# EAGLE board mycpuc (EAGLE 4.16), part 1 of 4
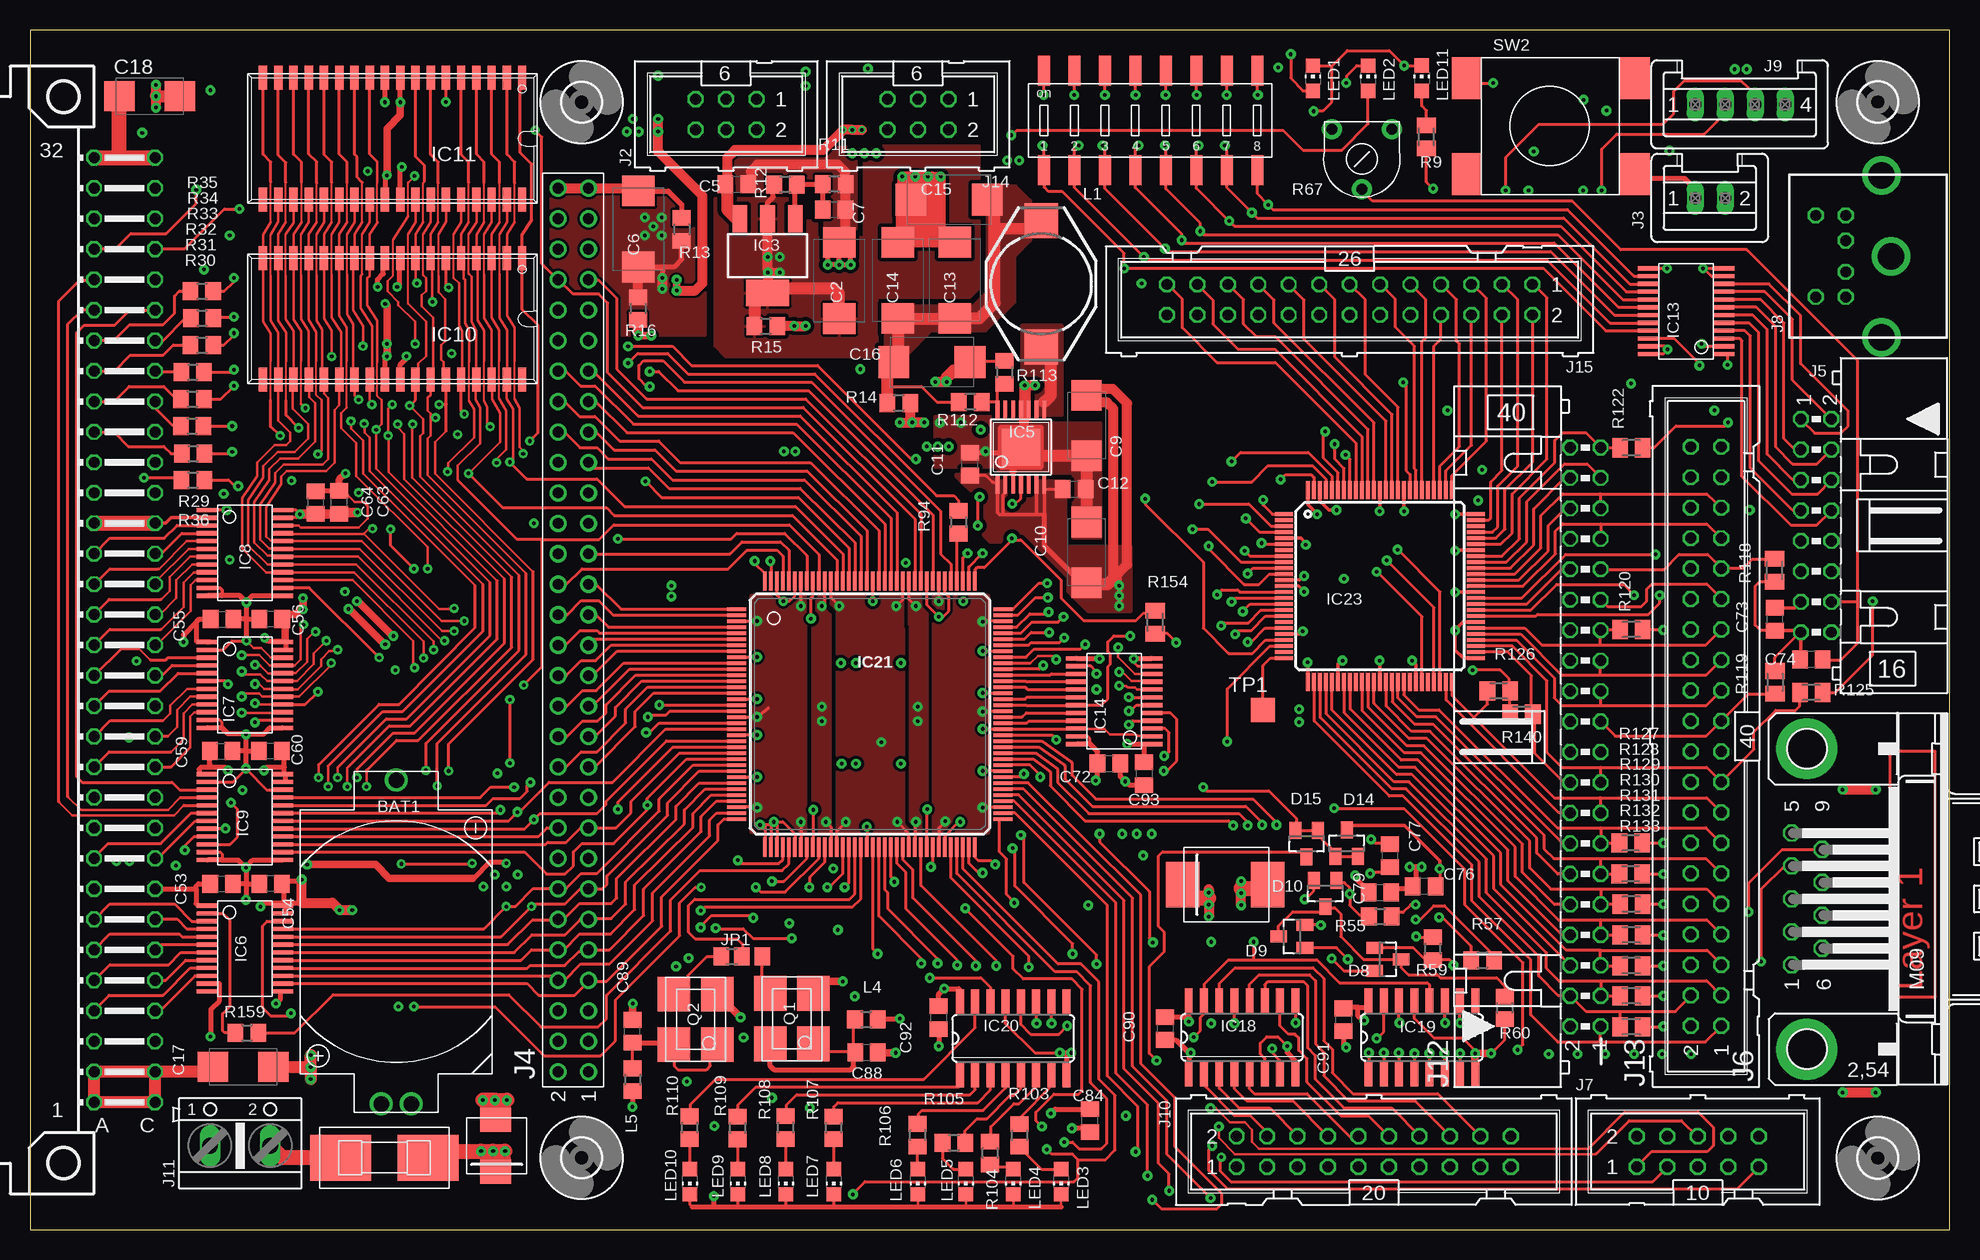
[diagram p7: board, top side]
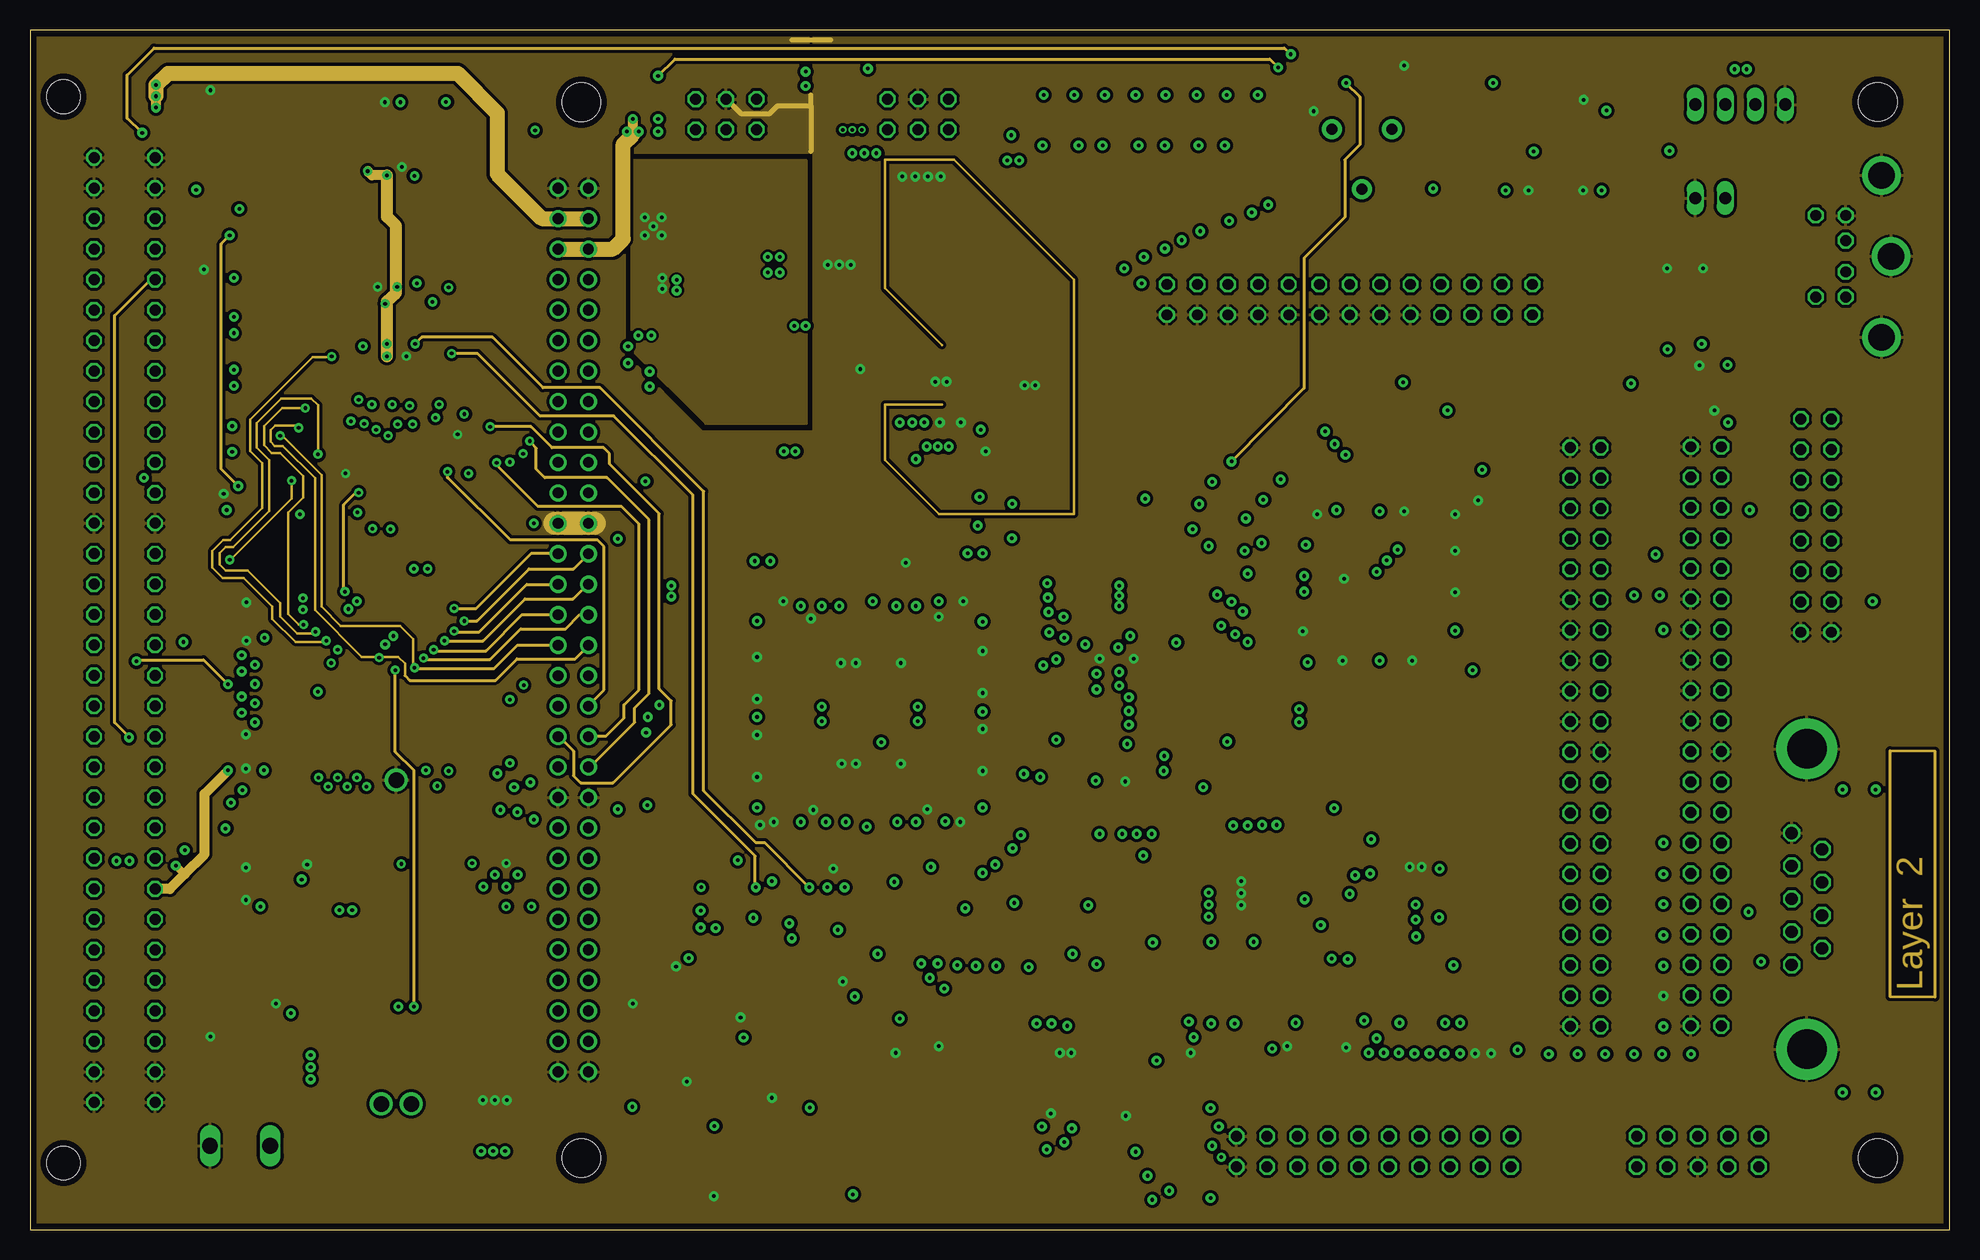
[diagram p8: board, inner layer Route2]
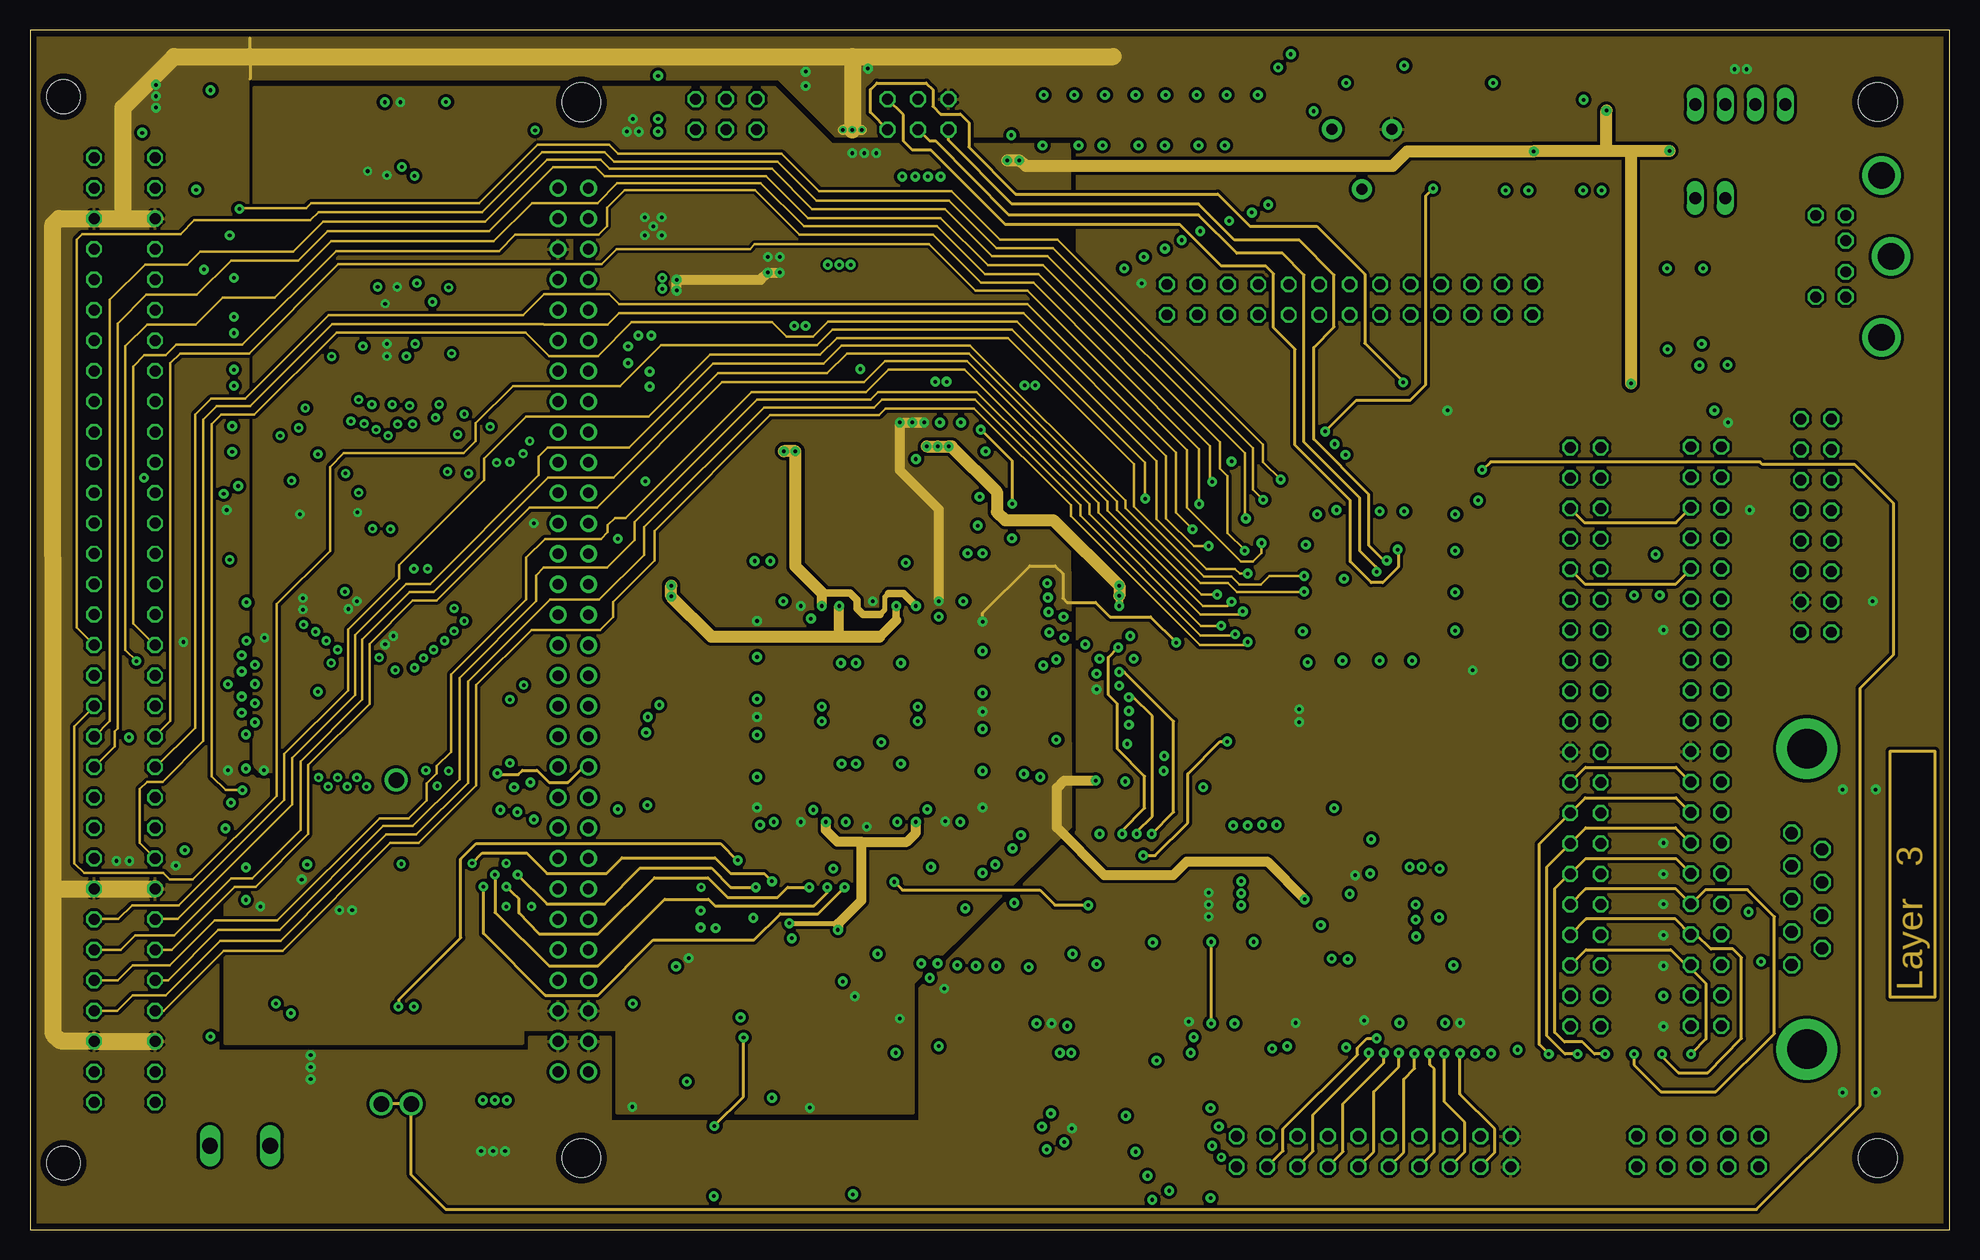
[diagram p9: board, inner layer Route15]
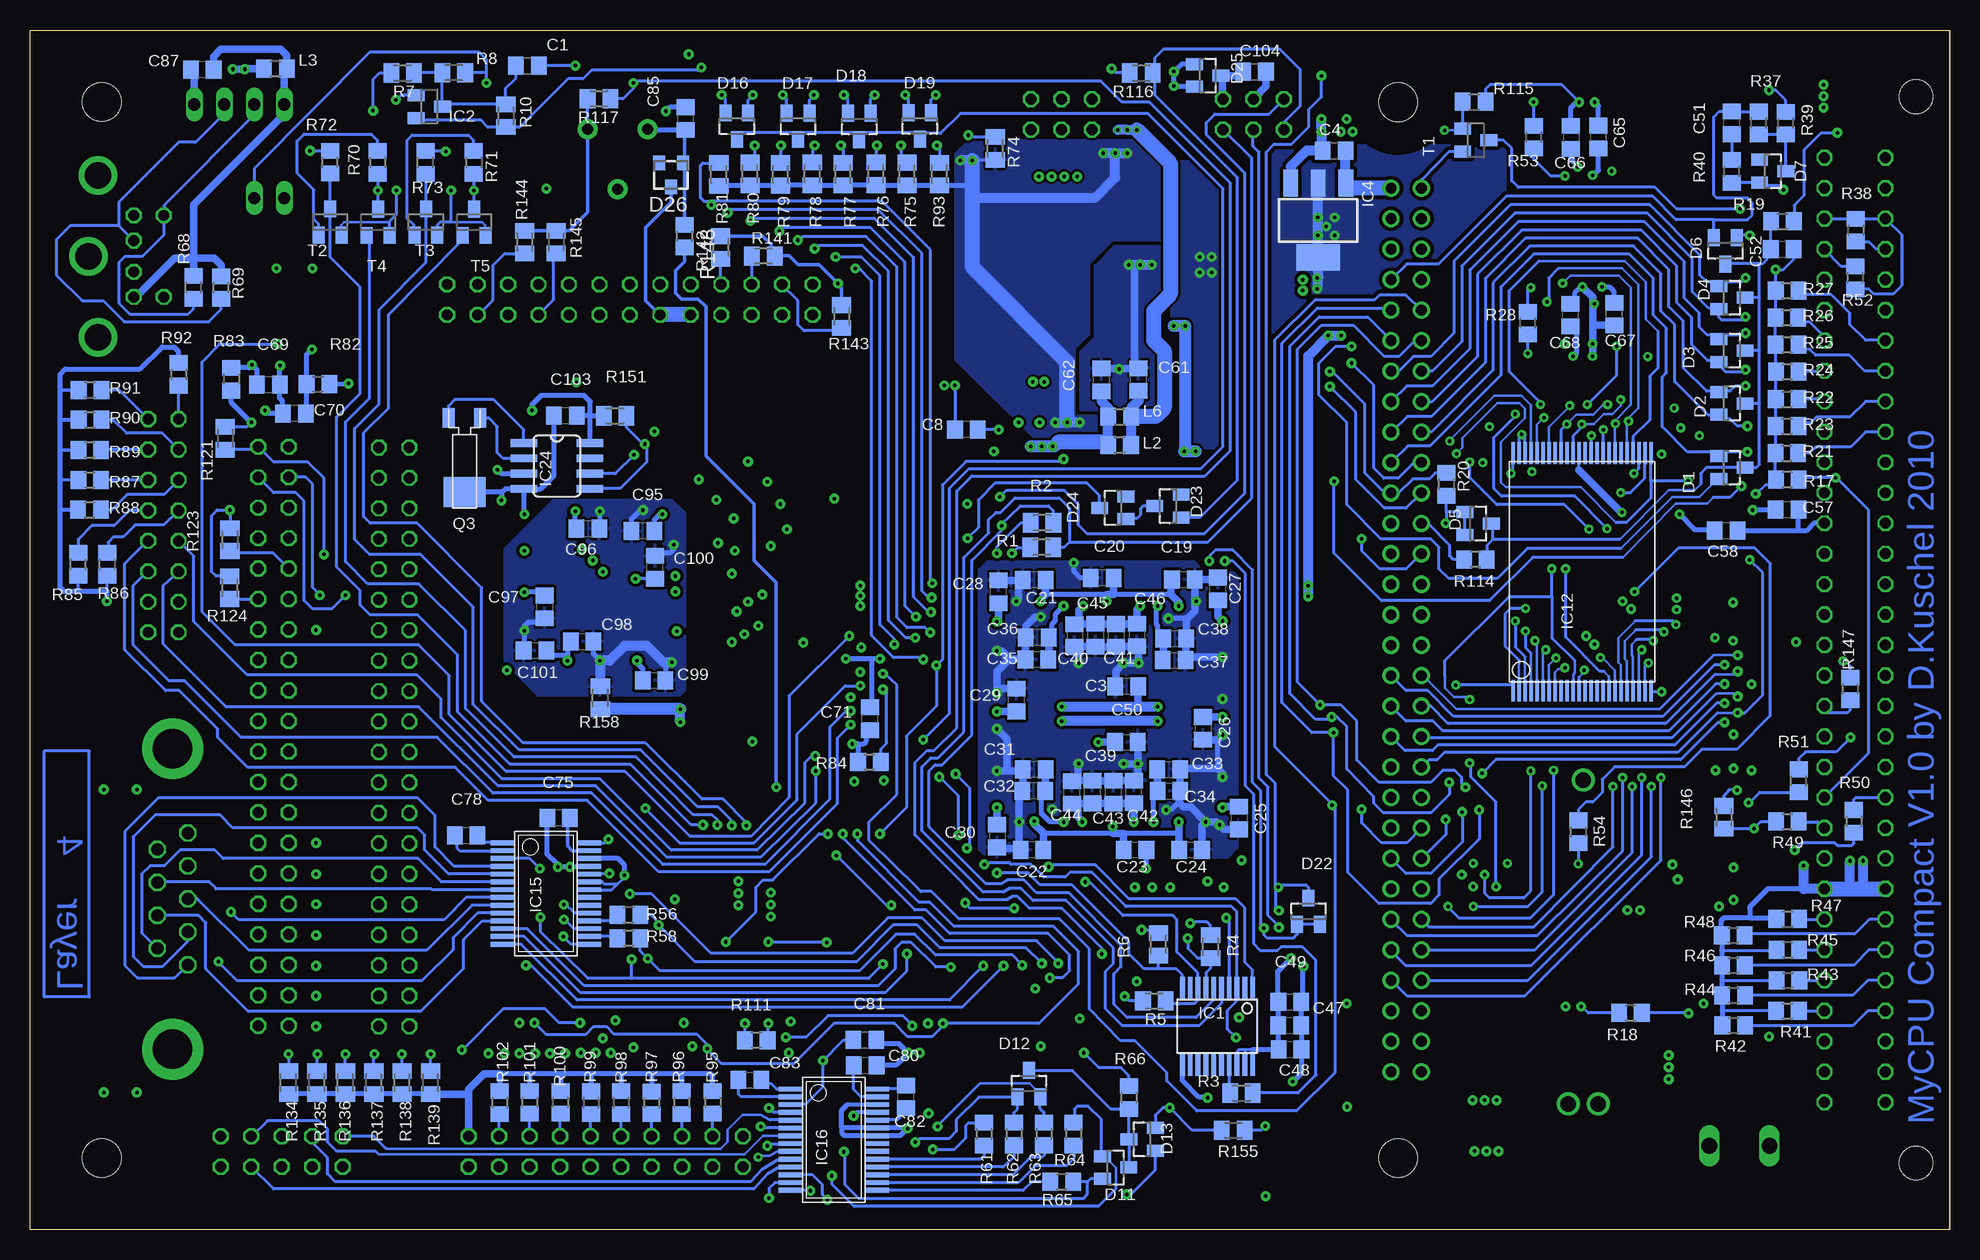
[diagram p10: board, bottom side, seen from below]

Size 160 x 100.03 mm. Coordinates in mm from the lower left corner, seen from the top.
Outline: 0,0.01 160,0.01 160,100.01 0,100.01 0,0.01
Copper layers (1+2*15+16): Top 0.035mm / dielectric 0.36mm / Route2 0.035mm / dielectric 0.71mm / Route15 0.035mm / dielectric 0.36mm / Bottom 0.035mm
Design rules "LeitOn_4layers_neu": minimum track width 6mil, minimum drill 0.3mm, track to track 8mil, track to pad 7mil, pad to pad 6mil, via to via 8mil, smd to smd 6mil, copper to edge 20mil, drill to drill 10mil, minimum pad ring 8mil, minimum via ring 6mil, stop-mask expansion 3mil, vias tented up to drill 0mil, thermal gap 8mil

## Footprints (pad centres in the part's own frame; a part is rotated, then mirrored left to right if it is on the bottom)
BATH = drill 1.3 pad 1.93 round: NEG -2.5,8; POS1 24.5,9.25; POS2 24.5,6.75
C0805 = smd 1.3 x 1.5: 1 -0.95,0; 2 0.95,0
D/7343-31R = smd 2.55 x 2.7: + 3.175,0; - -3.175,0
C/6032-28R = smd 2.55 x 2.5: + 2.525,0; - -2.525,0
SOT23 = smd 1 x 1.4: 1 -0.95,-1.1; 2 0.95,-1.1; 3 0,1.1
DO214AB = smd 2.8 x 3.8: A -3.5,0; K 3.6,0
DO214AA = smd 2 x 2.6: A -2.1,0; K 2.2,0
TO236 = smd 1 x 1.2: A -1,-1; C 0,1; NC 1,-1
HASF = smd 5.08 x 3.81: 1 -3.651,0; 2 3.651,0
3,2 = hole 3.2: 0,0
VO20 = smd 0.4 x 1.8: 1 5.85,6.15; 2 5.2,6.15; 3 4.55,6.15; 4 3.9,6.15; 5 3.25,6.15; 6 2.6,6.15; 7 1.95,6.15; 8 1.3,6.15; 9 0.65,6.15; 10 0,6.15; 11 0,-0.3; 12 0.65,-0.3; 13 1.3,-0.3; 14 1.95,-0.3; 15 2.6,-0.3; 16 3.25,-0.3; 17 3.9,-0.3; 18 4.55,-0.3; 19 5.2,-0.3; 20 5.85,-0.3
SOT223 = smd 1.219 x 2.235: 1 -2.311,-3.099; 2 0,-3.099; 3 2.311,-3.099 | smd 3.6 x 2.2: 4 0,3.099
ETSSOP14 = smd 0.31 x 1.5: 1 -1.95,-3.118; 2 -1.3,-3.118; 3 -0.65,-3.118; 4 0,-3.118; 5 0.65,-3.118; 6 1.3,-3.118; 7 1.95,-3.118; 8 1.95,3.118; 9 1.3,3.118; 10 0.65,3.118; 11 0,3.118; 12 -0.65,3.118; 13 -1.3,3.118; 14 -1.95,3.118 | smd 3.2 x 3.1: 15 0,0
TSSOP24 = smd 0.35 x 1.8: 1 0,-0.2; 2 0.65,-0.2; 3 1.3,-0.2; 4 1.95,-0.2; 5 2.6,-0.2; 6 3.25,-0.2; 7 3.9,-0.2; 8 4.55,-0.2; 9 5.2,-0.2; 10 5.85,-0.2; 11 6.5,-0.2; 12 7.15,-0.2; 13 7.15,6.05; 14 6.5,6.05; 15 5.85,6.05; 16 5.2,6.05; 17 4.55,6.05; 18 3.9,6.05; 19 3.25,6.05; 20 2.6,6.05; 21 1.95,6.05; 22 1.3,6.05; 23 0.65,6.05; 24 0,6.05
SOJ36 = smd 0.7 x 2: 1 0,0; 2 1.27,0; 3 2.54,0; 4 3.81,0; 5 5.08,0; 6 6.35,0; 7 7.62,0; 8 8.89,0; 9 10.16,0; 10 11.43,0; 11 12.7,0; 12 13.97,0; 13 15.24,0; 14 16.51,0; 15 17.78,0; 16 19.05,0; 17 20.32,0; 18 21.59,0; 19 21.59,10.16; 20 20.32,10.16; 21 19.05,10.16; 22 17.78,10.16; 23 16.51,10.16; 24 15.24,10.16; 25 13.97,10.16; 26 12.7,10.16; 27 11.43,10.16; 28 10.16,10.16; 29 8.89,10.16; 30 7.62,10.16; 31 6.35,10.16; 32 5.08,10.16; 33 3.81,10.16; 34 2.54,10.16; 35 1.27,10.16; 36 0,10.16
TSOP48 = smd 0.3 x 1.8: 1 0,-0.1; 2 0.5,-0.1; 3 1,-0.1; 4 1.5,-0.1; 5 2,-0.1; 6 2.5,-0.1; 7 3,-0.1; 8 3.5,-0.1; 9 4,-0.1; 10 4.5,-0.1; 11 5,-0.1; 12 5.5,-0.1; 13 6,-0.1; 14 6.5,-0.1; 15 7,-0.1; 16 7.5,-0.1; 17 8,-0.1; 18 8.5,-0.1; 19 9,-0.1; 20 9.5,-0.1; 21 10,-0.1; 22 10.5,-0.1; 23 11,-0.1; 24 11.5,-0.1; 25 11.5,19.7; 26 11,19.7; 27 10.5,19.7; 28 10,19.7; 29 9.5,19.7; 30 9,19.7; 31 8.5,19.7; 32 8,19.7; 33 7.5,19.7; 34 7,19.7; 35 6.5,19.7; 36 6,19.7; 37 5.5,19.7; 38 5,19.7; 39 4.5,19.7; 40 4,19.7; 41 3.5,19.7; 42 3,19.7; 43 2.5,19.7; 44 2,19.7; 45 1.5,19.7; 46 1,19.7; 47 0.5,19.7; 48 0,19.7
SSOP28 = smd 0.4 x 2: 1 -4.225,-3.612; 2 -3.575,-3.612; 3 -2.925,-3.612; 4 -2.275,-3.612; 5 -1.625,-3.612; 6 -0.975,-3.612; 7 -0.325,-3.612; 8 0.325,-3.612; 9 0.975,-3.612; 10 1.625,-3.612; 11 2.275,-3.612; 12 2.925,-3.612; 13 3.575,-3.612; 14 4.225,-3.612; 15 4.225,3.612; 16 3.575,3.612; 17 2.925,3.612; 18 2.275,3.612; 19 1.625,3.612; 20 0.975,3.612; 21 0.325,3.612; 22 -0.325,3.612; 23 -0.975,3.612; 24 -1.625,3.612; 25 -2.275,3.612; 26 -2.925,3.612; 27 -3.575,3.612; 28 -4.225,3.612
SO16 = smd 0.66 x 2.032: 1 -4.445,-3.073; 2 -3.175,-3.073; 3 -1.905,-3.073; 4 -0.635,-3.073; 5 0.635,-3.073; 6 1.905,-3.073; 7 3.175,-3.073; 8 4.445,-3.073; 9 4.445,3.073; 10 3.175,3.073; 11 1.905,3.073; 12 0.635,3.073; 13 -0.635,3.073; 14 -1.905,3.073; 15 -3.175,3.073; 16 -4.445,3.073
TQ144 = smd 1.6 x 0.3: P1 -11.1,8.75; P2 -11.1,8.25; P3 -11.1,7.75; P4 -11.1,7.25; P5 -11.1,6.75; P6 -11.1,6.25; P7 -11.1,5.75; P8 -11.1,5.25; P9 -11.1,4.75; P10 -11.1,4.25; P11 -11.1,3.75; P12 -11.1,3.25; P13 -11.1,2.75; P14 -11.1,2.25; P15 -11.1,1.75; P16 -11.1,1.25; P17 -11.1,0.75; P18 -11.1,0.25; P19 -11.1,-0.25; P20 -11.1,-0.75; P21 -11.1,-1.25; P22 -11.1,-1.75; P23 -11.1,-2.25; P24 -11.1,-2.75; P25 -11.1,-3.25; P26 -11.1,-3.75; P27 -11.1,-4.25; P28 -11.1,-4.75; P29 -11.1,-5.25; P30 -11.1,-5.75; P31 -11.1,-6.25; P32 -11.1,-6.75; P33 -11.1,-7.25; P34 -11.1,-7.75; P35 -11.1,-8.25; P36 -11.1,-8.75; P73 11.1,-8.75; P74 11.1,-8.25; P75 11.1,-7.75; P76 11.1,-7.25; P77 11.1,-6.75; P78 11.1,-6.25; P79 11.1,-5.75; P80 11.1,-5.25; P81 11.1,-4.75; P82 11.1,-4.25; P83 11.1,-3.75; P84 11.1,-3.25; P85 11.1,-2.75; P86 11.1,-2.25; P87 11.1,-1.75; P88 11.1,-1.25; P89 11.1,-0.75; P90 11.1,-0.25; P91 11.1,0.25; P92 11.1,0.75; P93 11.1,1.25; P94 11.1,1.75; P95 11.1,2.25; P96 11.1,2.75; P97 11.1,3.25; P98 11.1,3.75; P99 11.1,4.25; P100 11.1,4.75; P101 11.1,5.25; P102 11.1,5.75; P103 11.1,6.25; P104 11.1,6.75; P105 11.1,7.25; P106 11.1,7.75; P107 11.1,8.25; P108 11.1,8.75 | smd 0.3 x 1.6: P37 -8.75,-11.1; P38 -8.25,-11.1; P39 -7.75,-11.1; P40 -7.25,-11.1; P41 -6.75,-11.1; P42 -6.25,-11.1; P43 -5.75,-11.1; P44 -5.25,-11.1; P45 -4.75,-11.1; P46 -4.25,-11.1; P47 -3.75,-11.1; P48 -3.25,-11.1; P49 -2.75,-11.1; P50 -2.25,-11.1; P51 -1.75,-11.1; P52 -1.25,-11.1; P53 -0.75,-11.1; P54 -0.25,-11.1; P55 0.25,-11.1; P56 0.75,-11.1; P57 1.25,-11.1; P58 1.75,-11.1; P59 2.25,-11.1; P60 2.75,-11.1; P61 3.25,-11.1; P62 3.75,-11.1; P63 4.25,-11.1; P64 4.75,-11.1; P65 5.25,-11.1; P66 5.75,-11.1; P67 6.25,-11.1; P68 6.75,-11.1; P69 7.25,-11.1; P70 7.75,-11.1; P71 8.25,-11.1; P72 8.75,-11.1; P109 8.75,11.1; P110 8.25,11.1; P111 7.75,11.1; P112 7.25,11.1; P113 6.75,11.1; P114 6.25,11.1; P115 5.75,11.1; P116 5.25,11.1; P117 4.75,11.1; P118 4.25,11.1; P119 3.75,11.1; P120 3.25,11.1; P121 2.75,11.1; P122 2.25,11.1; P123 1.75,11.1; P124 1.25,11.1; P125 0.75,11.1; P126 0.25,11.1; P127 -0.25,11.1; P128 -0.75,11.1; P129 -1.25,11.1; P130 -1.75,11.1; P131 -2.25,11.1; P132 -2.75,11.1; P133 -3.25,11.1; P134 -3.75,11.1; P135 -4.25,11.1; P136 -4.75,11.1; P137 -5.25,11.1; P138 -5.75,11.1; P139 -6.25,11.1; P140 -6.75,11.1; P141 -7.25,11.1; P142 -7.75,11.1; P143 -8.25,11.1; P144 -8.75,11.1
TQFP100 = smd 1.5 x 0.33: 1 -8,6; 2 -8,5.5; 3 -8,5; 4 -8,4.5; 5 -8,4; 6 -8,3.5; 7 -8,3; 8 -8,2.5; 9 -8,2; 10 -8,1.5; 11 -8,1; 12 -8,0.5; 13 -8,0; 14 -8,-0.5; 15 -8,-1; 16 -8,-1.5; 17 -8,-2; 18 -8,-2.5; 19 -8,-3; 20 -8,-3.5; 21 -8,-4; 22 -8,-4.5; 23 -8,-5; 24 -8,-5.5; 25 -8,-6; 51 8,-6; 52 8,-5.5; 53 8,-5; 54 8,-4.5; 55 8,-4; 56 8,-3.5; 57 8,-3; 58 8,-2.5; 59 8,-2; 60 8,-1.5; 61 8,-1; 62 8,-0.5; 63 8,0; 64 8,0.5; 65 8,1; 66 8,1.5; 67 8,2; 68 8,2.5; 69 8,3; 70 8,3.5; 71 8,4; 72 8,4.5; 73 8,5; 74 8,5.5; 75 8,6 | smd 0.33 x 1.5: 26 -6,-8; 27 -5.5,-8; 28 -5,-8; 29 -4.5,-8; 30 -4,-8; 31 -3.5,-8; 32 -3,-8; 33 -2.5,-8; 34 -2,-8; 35 -1.5,-8; 36 -1,-8; 37 -0.5,-8; 38 0,-8; 39 0.5,-8; 40 1,-8; 41 1.5,-8; 42 2,-8; 43 2.5,-8; 44 3,-8; 45 3.5,-8; 46 4,-8; 47 4.5,-8; 48 5,-8; 49 5.5,-8; 50 6,-8; 76 6,8; 77 5.5,8; 78 5,8; 79 4.5,8; 80 4,8; 81 3.5,8; 82 3,8; 83 2.5,8; 84 2,8; 85 1.5,8; 86 1,8; 87 0.5,8; 88 0,8; 89 -0.5,8; 90 -1,8; 91 -1.5,8; 92 -2,8; 93 -2.5,8; 94 -3,8; 95 -3.5,8; 96 -4,8; 97 -4.5,8; 98 -5,8; 99 -5.5,8; 100 -6,8
SO8 = smd 0.65 x 2.2: 1 -1.905,-2.756; 2 -0.635,-2.756; 3 0.635,-2.756; 4 1.905,-2.756; 5 1.905,2.756; 6 0.635,2.756; 7 -0.635,2.756; 8 -1.905,2.756
MAC64L = drill 0.914 octagon: A1 -2.54,39.37; A2 -2.54,36.83; A3 -2.54,34.29; A4 -2.54,31.75; A5 -2.54,29.21; A6 -2.54,26.67; A7 -2.54,24.13; A8 -2.54,21.59; A9 -2.54,19.05; A10 -2.54,16.51; A11 -2.54,13.97; A12 -2.54,11.43; A13 -2.54,8.89; A14 -2.54,6.35; A15 -2.54,3.81; A16 -2.54,1.27; A17 -2.54,-1.27; A18 -2.54,-3.81; A19 -2.54,-6.35; A20 -2.54,-8.89; A21 -2.54,-11.43; A22 -2.54,-13.97; A23 -2.54,-16.51; A24 -2.54,-19.05; A25 -2.54,-21.59; A26 -2.54,-24.13; A27 -2.54,-26.67; A28 -2.54,-29.21; A29 -2.54,-31.75; A30 -2.54,-34.29; A31 -2.54,-36.83; A32 -2.54,-39.37; C1 -7.62,39.37; C2 -7.62,36.83; C3 -7.62,34.29; C4 -7.62,31.75; C5 -7.62,29.21; C6 -7.62,26.67; C7 -7.62,24.13; C8 -7.62,21.59; C9 -7.62,19.05; C10 -7.62,16.51; C11 -7.62,13.97; C12 -7.62,11.43; C13 -7.62,8.89; C14 -7.62,6.35; C15 -7.62,3.81; C16 -7.62,1.27; C17 -7.62,-1.27; C18 -7.62,-3.81; C19 -7.62,-6.35; C20 -7.62,-8.89; C21 -7.62,-11.43; C22 -7.62,-13.97; C23 -7.62,-16.51; C24 -7.62,-19.05; C25 -7.62,-21.59; C26 -7.62,-24.13; C27 -7.62,-26.67; C28 -7.62,-29.21; C29 -7.62,-31.75; C30 -7.62,-34.29; C31 -7.62,-36.83; C32 -7.62,-39.37 | hole 2.794: 0,44.45; 0,-44.45
ML6 = drill 0.914 octagon: 1 -2.54,-1.27; 2 -2.54,1.27; 3 0,-1.27; 4 0,1.27; 5 2.54,-1.27; 6 2.54,1.27
S02P = drill 1.016 long: 1 1.25,0; 2 -1.25,0
DIL2X30 = drill 0.9 pad 1.422 round: 1 0,0; 2 0,2.54; 3 2.54,0; 4 2.54,2.54; 5 5.08,0; 6 5.08,2.54; 7 7.62,0; 8 7.62,2.54; 9 10.16,0; 10 10.16,2.54; 11 12.7,0; 12 12.7,2.54; 13 15.24,0; 14 15.24,2.54; 15 17.78,0; 16 17.78,2.54; 17 20.32,0; 18 20.32,2.54; 19 22.86,0; 20 22.86,2.54; 21 25.4,0; 22 25.4,2.54; 23 27.94,0; 24 27.94,2.54; 25 30.48,0; 26 30.48,2.54; 27 33.02,0; 28 33.02,2.54; 29 35.56,0; 30 35.56,2.54; 31 38.1,0; 32 38.1,2.54; 33 40.64,0; 34 40.64,2.54; 35 43.18,0; 36 43.18,2.54; 37 45.72,0; 38 45.72,2.54; 39 48.26,0; 40 48.26,2.54; 41 50.8,0; 42 50.8,2.54; 43 53.34,0; 44 53.34,2.54; 45 55.88,0; 46 55.88,2.54; 47 58.42,0; 48 58.42,2.54; 49 60.96,0; 50 60.96,2.54; 51 63.5,0; 52 63.5,2.54; 53 66.04,0; 54 66.04,2.54; 55 68.58,0; 56 68.58,2.54; 57 71.12,0; 58 71.12,2.54; 59 73.66,0; 60 73.66,2.54
ML16L = drill 0.914 octagon: 1 -8.89,-1.27; 2 -8.89,1.27; 3 -6.35,-1.27; 4 -6.35,1.27; 5 -3.81,-1.27; 6 -3.81,1.27; 7 -1.27,-1.27; 8 -1.27,1.27; 9 1.27,-1.27; 10 1.27,1.27; 11 3.81,-1.27; 12 3.81,1.27; 13 6.35,-1.27; 14 6.35,1.27; 15 8.89,-1.27; 16 8.89,1.27
M09HP = drill 1.016 octagon: 1 -5.486,1.27; 2 -2.743,1.27; 3 0,1.27; 4 2.743,1.27; 5 5.486,1.27; 6 -4.115,-1.27; 7 -1.372,-1.27; 8 1.372,-1.27; 9 4.115,-1.27 | drill 3.302 pad 5.08 round: G1 -12.522,0; G2 12.522,0
ML10 = drill 0.914 octagon: 1 -5.08,-1.27; 2 -5.08,1.27; 3 -2.54,-1.27; 4 -2.54,1.27; 5 0,-1.27; 6 0,1.27; 7 2.54,-1.27; 8 2.54,1.27; 9 5.08,-1.27; 10 5.08,1.27
MINIDIN-6 = drill 0.9 octagon: 1 1.3,1.788; 2 -1.3,1.788; 3 3.4,1.788; 4 -3.4,1.788; 5 3.4,4.287; 6 -3.4,4.287 | drill 2.2 pad 3.2 round: SHIELD.1 0,-2; SHIELD.2 6.75,-1.2; SHIELD.3 -6.75,-1.2
S04P = drill 1.016 long: 1 3.75,0; 2 1.25,0; 3 -1.25,0; 4 -3.75,0
ML20 = drill 0.914 octagon: 1 -11.43,-1.27; 2 -11.43,1.27; 3 -8.89,-1.27; 4 -8.89,1.27; 5 -6.35,-1.27; 6 -6.35,1.27; 7 -3.81,-1.27; 8 -3.81,1.27; 9 -1.27,-1.27; 10 -1.27,1.27; 11 1.27,-1.27; 12 1.27,1.27; 13 3.81,-1.27; 14 3.81,1.27; 15 6.35,-1.27; 16 6.35,1.27; 17 8.89,-1.27; 18 8.89,1.27; 19 11.43,-1.27; 20 11.43,1.27
AK500/2 = drill 1.321 long: 1 -2.515,0; 2 2.515,0
ML40L = drill 0.914 octagon: 1 -24.13,-1.27; 2 -24.13,1.27; 3 -21.59,-1.27; 4 -21.59,1.27; 5 -19.05,-1.27; 6 -19.05,1.27; 7 -16.51,-1.27; 8 -16.51,1.27; 9 -13.97,-1.27; 10 -13.97,1.27; 11 -11.43,-1.27; 12 -11.43,1.27; 13 -8.89,-1.27; 14 -8.89,1.27; 15 -6.35,-1.27; 16 -6.35,1.27; 17 -3.81,-1.27; 18 -3.81,1.27; 19 -1.27,-1.27; 20 -1.27,1.27; 21 1.27,-1.27; 22 1.27,1.27; 23 3.81,-1.27; 24 3.81,1.27; 25 6.35,-1.27; 26 6.35,1.27; 27 8.89,-1.27; 28 8.89,1.27; 29 11.43,-1.27; 30 11.43,1.27; 31 13.97,-1.27; 32 13.97,1.27; 33 16.51,-1.27; 34 16.51,1.27; 35 19.05,-1.27; 36 19.05,1.27; 37 21.59,-1.27; 38 21.59,1.27; 39 24.13,-1.27; 40 24.13,1.27
ML40 = drill 0.914 octagon: 1 -24.13,-1.27; 2 -24.13,1.27; 3 -21.59,-1.27; 4 -21.59,1.27; 5 -19.05,-1.27; 6 -19.05,1.27; 7 -16.51,-1.27; 8 -16.51,1.27; 9 -13.97,-1.27; 10 -13.97,1.27; 11 -11.43,-1.27; 12 -11.43,1.27; 13 -8.89,-1.27; 14 -8.89,1.27; 15 -6.35,-1.27; 16 -6.35,1.27; 17 -3.81,-1.27; 18 -3.81,1.27; 19 -1.27,-1.27; 20 -1.27,1.27; 21 1.27,-1.27; 22 1.27,1.27; 23 3.81,-1.27; 24 3.81,1.27; 25 6.35,-1.27; 26 6.35,1.27; 27 8.89,-1.27; 28 8.89,1.27; 29 11.43,-1.27; 30 11.43,1.27; 31 13.97,-1.27; 32 13.97,1.27; 33 16.51,-1.27; 34 16.51,1.27; 35 19.05,-1.27; 36 19.05,1.27; 37 21.59,-1.27; 38 21.59,1.27; 39 24.13,-1.27; 40 24.13,1.27
ML26 = drill 0.914 octagon: 1 -15.24,-1.27; 2 -15.24,1.27; 3 -12.7,-1.27; 4 -12.7,1.27; 5 -10.16,-1.27; 6 -10.16,1.27; 7 -7.62,-1.27; 8 -7.62,1.27; 9 -5.08,-1.27; 10 -5.08,1.27; 11 -2.54,-1.27; 12 -2.54,1.27; 13 0,-1.27; 14 0,1.27; 15 2.54,-1.27; 16 2.54,1.27; 17 5.08,-1.27; 18 5.08,1.27; 19 7.62,-1.27; 20 7.62,1.27; 21 10.16,-1.27; 22 10.16,1.27; 23 12.7,-1.27; 24 12.7,1.27; 25 15.24,-1.27; 26 15.24,1.27
A0R-JMP = smd 1.5 x 1.3: 1 0,1.7; 2 0,0; 3 0,-1.7
DO3316P = smd 2.92 x 2.79: 1 -5.28,0; 2 5.28,0
0805 = smd 1.3 x 1.5: 1 -0.95,0; 2 0.95,0
CHIP-LED0805 = smd 1.2 x 1.2: A 0,-1.05; C 0,1.05
XO91 = smd 2.9 x 2.7: 1 1.4,0.7; 2 5.6,0.7; 3 5.6,4.3; 4 1.4,4.3
MS1V = smd 1.6 x 1: 1 4.2,-1.3; 2 4.2,1.3 | smd 2.5 x 3.5: GND -2,0
M0805 = smd 1.3 x 1.6: 1 -0.95,0; 2 0.95,0
R0805 = smd 1.3 x 1.5: 1 -0.95,0; 2 0.95,0
PT-6L = drill 0.9 pad 1.676 round: 1 -2.5,-2.5; 2 0,2.5; 3 2.5,-2.5
DIPSW08 = smd 1 x 2.5: 1 0,0.318; 2 2.54,0.318; 3 5.08,0.318; 4 7.62,0.318; 5 10.16,0.318; 6 12.7,0.318; 7 15.24,0.318; 8 17.78,0.318; 9 17.78,8.572; 10 15.24,8.572; 11 12.7,8.572; 12 10.16,8.572; 13 7.62,8.572; 14 5.08,8.572; 15 2.54,8.572; 16 0,8.572
DIGIKEY-1 = smd 2.5 x 3.5: 1 -1.2,9.7; 2 12.8,1.7; NC.1 -1.2,1.7; NC.2 12.8,9.7
TEST-PAD = smd 2 x 2: P$1 0,0

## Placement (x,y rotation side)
BAT1  CR2032  [BATH]  22.53,35 270 top
C1  220nF  [C0805]  118.55,97.05 0 bottom
C2  47uF/10V/D  [D/7343-31R]  67.47,79.14 270 top
C3  1uF/Ker  [C0805]  68.58,45.3 180 bottom
C4  1uF/Ker  [C0805]  51.29,89.97 0 bottom
C5  1uF/Ker  [C0805]  58.91,87.17 0 top
C6  47uF/10V/D  [D/7343-31R]  50.72,83.43 270 top
C7  1uF/Ker  [C0805]  67.03,85.07 0 top
C8  3.3nF  [C0805]  81.95,66.72 180 bottom
C9  22uF/16V/C  [C/6032-28R]  88.08,67.06 90 top
C10  22uF/16V/C  [C/6032-28R]  88.07,56.48 270 top
C11  1uF/Ker  [C0805]  78.34,63.83 90 top
C12  1uF/Ker  [C0805]  87.04,61.77 0 top
C13  47uF/10V/D  [D/7343-31R]  77.07,79.17 270 top
C14  47uF/10V/D  [D/7343-31R]  72.32,79.16 270 top
C15  47uF/10V/D  [D/7343-31R]  76.61,85.88 0 top
C16  47uF/10V/D  [D/7343-31R]  75.18,72.34 180 top
C17  22uF/16V/C  [C/6032-28R]  17.76,13.58 0 top
C18  22uF/16V/C  [C/6032-28R]  9.98,94.52 0 top
C19  1uF/Ker  [C0805]  63.86,54.22 0 bottom
C20  100nF  [C0805]  70.62,54.35 180 bottom
C21  10nF  [C0805]  76.3,54.18 180 bottom
C22  1uF/Ker  [C0805]  76.48,31.68 180 bottom
C23  100nF  [C0805]  67.89,31.69 0 bottom
C24  10nF  [C0805]  63.26,31.69 0 bottom
C25  1uF/Ker  [C0805]  59.23,34.33 270 bottom
C26  100nF  [C0805]  62.23,41.81 270 bottom
C27  10nF  [C0805]  60.97,53.43 90 bottom
C28  1uF/Ker  [C0805]  79.27,53.2 90 bottom
C29  100nF  [C0805]  77.77,44.17 90 bottom
C30  10nF  [C0805]  79.38,32.83 270 bottom
C31  100nF  [C0805]  76.3,38.38 180 bottom
C32  10nF  [C0805]  76.33,36.58 180 bottom
C33  100nF  [C0805]  65.09,38.39 0 bottom
C34  10nF  [C0805]  65.06,36.59 0 bottom
C35  100nF  [C0805]  76.07,47.53 180 bottom
C36  10nF  [C0805]  76.05,49.38 180 bottom
C37  100nF  [C0805]  64.62,47.49 0 bottom
C38  10nF  [C0805]  64.59,49.29 0 bottom
C39  100nF  [C0805]  71.43,36.5 90 bottom
C40  10nF  [C0805]  72.92,49.54 270 bottom
C41  100nF  [C0805]  69.47,49.56 270 bottom
C42  10nF  [C0805]  68,36.51 90 bottom
C43  100nF  [C0805]  69.7,36.49 90 bottom
C44  10nF  [C0805]  73.15,36.47 90 bottom
C45  100nF  [C0805]  71.2,49.57 270 bottom
C46  10nF  [C0805]  67.75,49.59 270 bottom
C47  1uF/Ker  [C0805]  55,17.06 0 bottom
C48  100nF  [C0805]  54.97,15.06 0 bottom
C49  10nF  [C0805]  54.99,19.01 0 bottom
C50  1uF/Ker  [C0805]  68.61,40.66 0 bottom
C51  100pF  [C0805]  18.15,92.29 90 bottom
C52  100nF  [C0805]  13.95,81.76 0 bottom
C53  100nF  [C0805]  15.97,28.86 0 top
C54  100nF  [C0805]  20.06,28.86 180 top
C55  100nF  [C0805]  16.01,50.91 0 top
C56  100nF  [C0805]  20.07,50.91 180 top
C57  100nF  [C0805]  13.55,60.06 0 bottom
C58  100nF  [C0805]  18.62,58.31 0 bottom
C59  100nF  [C0805]  15.94,39.91 0 top
C60  100nF  [C0805]  20.04,39.91 180 top
C61  100nF  [C0805]  67.6,70.88 90 bottom
C62  100nF  [C0805]  70.7,70.86 90 bottom
C63  100nF  [C0805]  25.78,60.66 90 top
C64  10nF  [C0805]  23.83,60.63 90 top
C65  100nF  [C0805]  29.25,91.1 90 bottom
C66  10nF  [C0805]  31.55,91.07 270 bottom
C67  100nF  [C0805]  27.93,76.34 90 bottom
C68  10nF  [C0805]  31.62,76.26 270 bottom
C69  100nF  [C0805]  140.12,70.48 0 bottom
C70  100nF  [C0805]  137.96,68.04 180 bottom
C71  100nF  [C0805]  89.98,42.62 90 bottom
C72  100nF  [C0805]  89.93,38.88 0 top
C73  100nF  [C0805]  145.42,50.91 270 top
C74  100nF  [C0805]  148.48,47.54 180 top
C75  1uF  [C0805]  115.94,34.34 180 bottom
C76  1uF  [C0805]  116.21,28.64 180 top
C77  220nF  [C0805]  113.37,31.19 90 top
C78  1uF  [C0805]  123.65,32.88 0 bottom
C79  220nF  [C0805]  112.52,28.13 0 top
C80  1uF  [C0805]  90.39,13.73 0 bottom
C81  1uF  [C0805]  90.41,15.83 0 bottom
C82  220nF  [C0805]  86.98,11.09 90 bottom
C83  1uF  [C0805]  100,12.49 0 bottom
C84  220nF  [C0805]  88.36,9.11 90 top
C85  100nF  [C0805]  105.34,92.64 90 bottom
C87  100nF  [C0805]  145.64,96.72 180 bottom
C88  100nF  [C0805]  69.73,14.8 0 top
C89  100nF  [C0805]  50.21,16.56 90 top
C90  100nF  [C0805]  94.59,16.79 270 top
C91  100nF  [C0805]  109.49,17.52 270 top
C92  100nF  [C0805]  75.74,17.7 270 top
C93  10nF  [C0805]  92.84,38.03 270 top
C95  100n  [C0805]  108.92,58.27 180 bottom
C96  100n  [C0805]  113.5,58.48 0 bottom
C97  100n  [C0805]  117.1,51.93 270 bottom
C98  100n  [C0805]  113.98,49.04 0 bottom
C99  100n  [C0805]  107.98,45.82 0 bottom
C100  100n  [C0805]  107.89,55.24 90 bottom
C101  100n  [C0805]  117.91,48.28 180 bottom
C103  100n  [C0805]  115.38,67.89 0 bottom
C104  1uF  [C0805]  57.93,96.55 0 bottom
D1  BAT54C  [SOT23]  18.14,63.54 270 bottom
D2  BAT54C  [SOT23]  18.14,68.9 270 bottom
D3  BAT54C  [SOT23]  18.14,73.31 270 bottom
D4  BAT54C  [SOT23]  18.14,77.72 270 bottom
D5  BAT54C  [SOT23]  39.29,58.88 270 bottom
D6  BAT54C  [SOT23]  18.68,81.62 180 bottom
D7  BAV70  [SOT23]  14.74,88.25 270 bottom
D8  BAT54C  [SOT23]  113.19,22.56 270 top
D9  BAT54C  [SOT23]  105.18,24.46 90 top
D10  BAT54C  [SOT23]  107.96,28.04 180 top
D11  BAT54C  [SOT23]  69.51,5.2 270 bottom
D12  BAT54C  [SOT23]  76.74,12.19 0 bottom
D13  BAT54C  [SOT23]  67.3,7.55 90 bottom
D14  BAT54C  [SOT23]  109.75,32.23 0 top
D15  BAT54C  [SOT23]  106.41,32.19 180 top
D16  BAT54C  [SOT23]  101.08,92.01 180 bottom
D17  BAT54C  [SOT23]  95.98,92 180 bottom
D18  BAT54C  [SOT23]  90.88,91.99 180 bottom
D19  BAT54C  [SOT23]  85.83,92.03 180 bottom
D20  MBRS340  [DO214AB]  99.68,28.77 180 top
D21  P6SMB68CA  [DO214AA]  38.8,7.06 270 top
D22  BAT54C  [SOT23]  53.43,26.56 0 bottom
D23  BAT54C  [SOT23]  65.15,60.34 90 bottom
D24  BAT54C  [SOT23]  69.74,60.19 90 bottom
D25  BAT54C  [SOT23]  61.83,96.23 270 bottom
D26  BZX84_3V9  [TO236]  106.57,87.94 180 bottom
F1  3A  [HASF]  29.53,6.01 180 top
H1  MOUNT-HOLE3.2  [3,2]  154.02,5.99 0 top
H2  MOUNT-HOLE3.2  [3,2]  45.97,6 0 top
H3  MOUNT-HOLE3.2  [3,2]  45.97,94.01 0 top
H4  MOUNT-HOLE3.2  [3,2]  154.02,94.02 0 top
IC1  XCF02S  [VO20]  63.94,14.06 0 bottom
IC2  MAX809TEUR  [SOT23]  126.71,93.64 270 bottom
IC3  LT1117-ADJ  [SOT223]  61.48,81.21 180 top
IC4  LT1117-ADJ  [SOT223]  52.62,84.16 180 bottom
IC5  LM2853  [ETSSOP14]  82.6,65.25 0 top
IC6  74LVC4245A  [TSSOP24]  15,27.03 270 top
IC7  74LVC4245A  [TSSOP24]  15,49 270 top
IC8  74LVC4245A  [TSSOP24]  15,60.02 270 top
IC9  74LVC4245A  [TSSOP24]  15,37.99 270 top
IC10  614008V-J  [SOJ36]  41.02,81.02 180 top
IC11  614008V-J  [SOJ36]  41.02,96.05 180 top
IC12  S29AL004D  [TSOP48]  36.38,45.06 0 bottom
IC13  74LVC4245A  [TSSOP24]  140.95,73.01 90 top
IC14  74LVC4245A  [TSSOP24]  93.3,40.49 90 top
IC15  MAX3245ECAI  [SSOP28]  117,28.03 270 bottom
IC16  MAX3245ECAI  [SSOP28]  93,7.52 270 bottom
IC18  74HC166D  [SO16]  101.03,16.06 0 top
IC19  74HC595D  [SO16]  116.02,16.06 0 top
IC20  74HC595D  [SO16]  81.96,15.97 0 top
IC21  XC3S400TQ144  [TQ144]  70,43 0 top
IC23  XC9572TQ100  [TQFP100]  112.53,53.66 0 top
IC24  DS1307Z  [SO8]  116.08,63.68 270 bottom
J1  MAC64L  [MAC64L]  2.8,50.01 180 top
J2  [ML6]  58.03,93 180 top
J3  [S02P]  140.06,86.02 180 top
J4  [DIL2X30]  46.55,13.18 90 top
J5  [ML16L]  148.89,58.71 270 top
J6  [M09HP]  148.11,27.59 90 top
J7  [ML10]  139.01,6.53 0 top
J8  PS2CONN  [MINIDIN-6]  153.14,81.17 90 top
J9  [S04P]  142.55,93.82 180 top
J10  [ML20]  112.01,6.53 0 top
J11  [AK500/2]  17.52,7.01 0 top
J12  [ML40L]  129.65,41.1 90 top
J13  [ML40]  139.7,41.15 90 top
J14  [ML6]  74.03,93 180 top
J15  [ML26]  110,77.55 180 top
JP1  0R-JUMPA  [A0R-JMP]  59.34,22.79 90 top
L1  6.8uH  [DO3316P]  84.3,78.87 90 top
L2  10nH  [0805]  69.18,65.44 0 bottom
L3  10nH  [0805]  139.55,96.78 180 bottom
L4  10nH  [0805]  69.72,17.54 0 top
L5  10nH  [0805]  50.23,12.52 270 top
L6  10nH  [0805]  69.16,67.78 0 bottom
LED1  [CHIP-LED0805]  106.94,96 0 top
LED2  [CHIP-LED0805]  111.54,96 0 top
LED3  [CHIP-LED0805]  85.96,4.02 180 top
LED4  [CHIP-LED0805]  81.96,4.02 180 top
LED5  [CHIP-LED0805]  78.01,4.02 180 top
LED6  [CHIP-LED0805]  74.01,4.02 180 top
LED7  [CHIP-LED0805]  67.01,4.02 180 top
LED8  [CHIP-LED0805]  63.01,4.02 180 top
LED9  [CHIP-LED0805]  59.01,4.02 180 top
LED10  [CHIP-LED0805]  55.01,4.02 180 top
LED11  [CHIP-LED0805]  116,96.01 0 top
Q1  24.000MHz  [XO91]  66,14.11 90 top
Q2  32.000MHz  [XO91]  57.98,14.05 90 top
Q3  MS1V-32KHZ  [MS1V]  123.79,63.49 90 bottom
R1  100  [M0805]  75.66,56.9 0 bottom
R2  100  [M0805]  75.64,58.95 0 bottom
R3  100  [M0805]  59.02,11.4 180 bottom
R4  4k7  [M0805]  61.59,23.61 270 bottom
R5  4k7  [M0805]  66.28,19.1 180 bottom
R6  2k2  [M0805]  65.94,23.8 270 bottom
R7  220  [M0805]  128.94,96.45 180 bottom
R8  560  [M0805]  124.68,96.47 0 bottom
R9  150  [M0805]  116.4,91.11 270 top
R10  NN  [M0805]  120.34,92.88 90 bottom
R11  39  [R0805]  67.04,87.18 180 top
R12  39  [R0805]  62.97,87.13 180 top
R13  220  [R0805]  54.33,83.41 270 top
R14  0  [R0805]  72.42,68.94 0 top
R15  0  [R0805]  61.34,75.34 0 top
R16  0  [R0805]  50.68,76.8 270 top
R17  4k7  [R0805]  13.52,62.53 180 bottom
R18  100  [R0805]  26.6,18.08 180 bottom
R19  150  [R0805]  13.93,84.08 0 bottom
R20  2k2  [R0805]  41.92,62.15 90 bottom
R21  4k7  [R0805]  13.56,64.74 0 bottom
R22  4k7  [R0805]  13.53,69.24 0 bottom
R23  4k7  [R0805]  13.55,66.99 0 bottom
R24  4k7  [R0805]  13.52,71.54 0 bottom
R25  4k7  [R0805]  13.54,73.79 0 bottom
R26  4k7  [R0805]  13.56,76.04 0 bottom
R27  4k7  [R0805]  13.53,78.29 0 bottom
R28  220  [R0805]  35.15,75.59 90 bottom
R29  4k7  [R0805]  13.6,64.71 0 top
R30  4k7  [R0805]  13.52,67.01 0 top
R31  4k7  [R0805]  13.54,69.26 0 top
R32  4k7  [R0805]  13.56,71.51 0 top
R33  4k7  [R0805]  14.33,73.76 0 top
R34  4k7  [R0805]  14.35,76.01 0 top
R35  4k7  [R0805]  14.32,78.26 0 top
R36  4k7  [R0805]  13.59,62.51 0 top
R37  4k7  [R0805]  15.9,92.27 90 bottom
R38  1k  [R0805]  7.8,83.34 90 bottom
R39  10k  [R0805]  13.65,92.26 90 bottom
R40  330  [R0805]  18.15,88.24 90 bottom
R41  4k7  [R0805]  13.51,18.26 0 bottom
R42  4k7  [R0805]  17.99,17.06 0 bottom
R43  4k7  [R0805]  13.47,20.81 0 bottom
R44  4k7  [R0805]  18,19.56 0 bottom
R45  4k7  [R0805]  13.48,23.36 0 bottom
R46  4k7  [R0805]  18.01,22.06 0 bottom
R47  4k7  [R0805]  13.49,25.91 0 bottom
R48  4k7  [R0805]  18.03,24.56 0 bottom
R49  47  [R0805]  13.52,34.04 0 bottom
R50  47  [R0805]  7.97,34.06 270 bottom
R51  47  [R0805]  12.58,37.43 90 bottom
R52  1k  [R0805]  7.87,79.37 270 bottom
R53  220  [R0805]  34.66,91.09 90 bottom
R54  220  [R0805]  30.92,33.18 90 bottom
R55  2k2  [R0805]  112.55,26.13 0 top
R56  2k2  [R0805]  110.08,26.24 180 bottom
R57  2k2  [R0805]  121.09,22.48 0 top
R58  2k2  [R0805]  110.09,24.29 180 bottom
R59  2k2  [R0805]  116.93,23.44 90 top
R60  470  [R0805]  122.92,18.51 270 top
R61  2k2  [R0805]  80.47,7.99 270 bottom
R62  2k2  [R0805]  77.98,8 270 bottom
R63  2k2  [R0805]  75.47,8 270 bottom
R64  2k2  [R0805]  73.03,7.99 270 bottom
R65  2k2  [R0805]  74,3.99 180 bottom
R66  470  [R0805]  68.38,11.03 90 bottom
R67  10k  [PT-6L]  111.02,89.27 180 top
R68  2k2  [R0805]  146.37,78.57 90 bottom
R69  2k2  [R0805]  144.07,78.55 90 bottom
R70  22k  [R0805]  131.02,88.98 270 bottom
R71  22k  [R0805]  123.01,88.99 270 bottom
R72  4k7  [R0805]  134.99,89.01 90 bottom
R73  4k7  [R0805]  127.04,88.99 90 bottom
R74  150  [M0805]  79.54,90.15 270 bottom
R75  10k  [M0805]  86.89,88.02 270 bottom
R76  10k  [M0805]  89.49,88.04 270 bottom
R77  10k  [M0805]  92.24,88.01 270 bottom
R78  10k  [M0805]  94.79,88.03 270 bottom
R79  10k  [M0805]  97.44,88 270 bottom
R80  10k  [M0805]  99.99,88.02 270 bottom
R81  10k  [M0805]  102.59,87.99 270 bottom
R82  47  [R0805]  135.99,70.5 0 bottom
R83  47  [R0805]  143.21,70.92 270 bottom
R84  47  [R0805]  90.03,39 0 bottom
R85  10k  [R0805]  155.98,55.49 90 bottom
R86  10k  [R0805]  153.55,55.49 90 bottom
R87  10k  [R0805]  155.02,62.51 0 bottom
R88  10k  [R0805]  155.04,60.03 0 bottom
R89  10k  [R0805]  155.02,65.02 0 bottom
R90  10k  [R0805]  154.99,67.53 0 bottom
R91  10k  [R0805]  154.99,70.02 0 bottom
R92  10k  [R0805]  147.61,71.33 270 bottom
R93  10k  [M0805]  84.19,88.01 270 bottom
R94  47  [R0805]  77.39,59 270 top
R95  10k  [R0805]  103.09,10.63 270 bottom
R96  10k  [R0805]  105.69,10.61 270 bottom
R97  10k  [R0805]  108.19,10.59 270 bottom
R98  10k  [R0805]  110.74,10.62 270 bottom
R99  10k  [R0805]  113.24,10.6 270 bottom
R100  10k  [R0805]  115.79,10.63 270 bottom
R101  10k  [R0805]  118.36,10.63 270 bottom
R102  10k  [R0805]  120.86,10.61 270 bottom
R103  470  [R0805]  82.49,7.88 90 top
R104  470  [R0805]  80.04,6.4 90 top
R105  470  [R0805]  77.01,7.27 0 top
R106  470  [R0805]  73.99,7.89 90 top
R107  470  [R0805]  66.99,8.51 90 top
R108  470  [R0805]  62.99,8.53 90 top
R109  470  [R0805]  58.99,8.5 90 top
R110  470  [R0805]  54.99,8.52 90 top
R111  390  [R0805]  99.47,15.8 180 bottom
R112  150  [R0805]  78.37,69.02 180 top
R113  4k7  [R0805]  81.22,71.48 270 top
R114  560  [R0805]  39.52,55.89 180 bottom
R115  4k7  [R0805]  39.63,94.03 0 bottom
R116  2k2  [M0805]  67.37,96.44 180 bottom
R117  NN  [M0805]  112.57,94.29 180 bottom
R118  10k  [M0805]  145.42,54.98 270 top
R119  10k  [M0805]  145.45,45.64 90 top
R120  4k7  [M0805]  133.48,50.04 0 top
R121  10k  [M0805]  143.74,65.99 90 bottom
R122  10k  [M0805]  133.48,65.2 0 top
R123  4k7  [M0805]  143.33,57.54 90 bottom
R124  1k  [M0805]  143.35,53.54 90 bottom
R125  10k  [M0805]  148.48,44.79 0 top
R126  10k  [M0805]  122.43,44.92 0 top
R127  10k  [M0805]  133.43,32.25 0 top
R128  10k  [M0805]  133.43,29.68 0 top
R129  10k  [M0805]  133.48,27.16 0 top
R130  10k  [M0805]  133.48,24.59 0 top
R131  10k  [M0805]  133.48,22.02 0 top
R132  10k  [M0805]  133.48,19.5 0 top
R133  10k  [M0805]  133.48,16.93 0 top
R134  10k  [M0805]  138.45,12.28 270 bottom
R135  10k  [M0805]  136.08,12.28 270 bottom
R136  10k  [M0805]  133.71,12.28 270 bottom
R137  10k  [M0805]  131.34,12.28 270 bottom
R138  10k  [M0805]  128.97,12.28 270 bottom
R139  10k  [M0805]  126.6,12.28 270 bottom
R140  10k  [M0805]  124.32,42.98 180 top
R141  10k  [M0805]  98.87,81.18 0 bottom
R142  10k  [M0805]  102.44,81.89 90 bottom
R143  10k  [M0805]  92.36,76.14 90 bottom
R144  10k  [M0805]  118.78,82.34 90 bottom
R145  10k  [M0805]  116.15,82.34 90 bottom
R146  47  [M0805]  18.82,34.39 90 bottom
R147  47  [R0805]  8.26,45.09 90 bottom
R148  470  [R0805]  105.45,82.84 270 bottom
R151  4k7  [M0805]  111.23,67.87 180 bottom
R154  2k2  [M0805]  93.8,50.65 270 top
R155  4k7  [M0805]  59.7,8.31 180 bottom
R158  0  [M0805]  112.46,44.36 270 bottom
R159  100  [R0805]  18.08,16.43 0 top
SW1  DIPSW08-SMD  [DIPSW08]  84.52,88.04 0 top
SW2  KEY-SMS-G  [DIGIKEY-1]  120.96,86.32 0 top
T1  BCR135  [SOT23]  39.49,90.84 270 bottom
T2  BCR135  [SOT23]  134.99,84.02 0 bottom
T3  BCR135  [SOT23]  127,84.02 0 bottom
T4  BCR135  [SOT23]  130.99,84 0 bottom
T5  BCR135  [SOT23]  122.98,84 0 bottom
TP1  TESTPAD1  [TEST-PAD]  102.78,43.33 0 top

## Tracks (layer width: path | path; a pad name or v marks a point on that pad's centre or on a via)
1_CTS
  Bottom 0.254: 149.4,28.96 | 149.4,28.96 J6.8 | 149.4,28.96 149.35,29.01 145.05,29.01 144.5,28.46 144.55,28.46 144.5,28.41 126.55,28.41 126.5,28.35 IC15.7
1_DCD
  Bottom 0.254: J6.1 | J6.1 147.95,21.01 151.05,21.01 152.1,22.06 152.1,33.21 149.3,36.01 127.7,36.01 126.25,34.56 126.25,31.91 124.64,30.3 IC15.4 | J6.1 146.8,22.16
1_DSR
  Bottom 0.254: J6.6 149.4,23.46 150.7,24.76 150.7,29.66 150,30.36 148.8,30.36 147.5,31.66 144.6,31.66 143.9,30.96 127.65,30.96 125.69,29 IC15.6
1_DTR  (via drill 0.3 pad 0.81)
  Top 0.254: v144.3,22.36 144.3,28.41 146.25,30.36 146.85,30.36 146.84,30.35 J6.4
  Bottom 0.254: IC15.10 122.7,26.4 124.75,24.36 124.75,23.36 127.35,20.76 142.75,20.76 v144.3,22.36
1_RI  (via drill 0.3 pad 0.81)
  Top 0.254: v143.25,26.51 143.25,28.91 146.05,31.71 149.4,31.71 149.44,31.7 J6.9
  Bottom 0.254: IC15.8 123.66,27.7 125.5,25.86 142.6,25.86 v143.25,26.51
1_RTS
  Bottom 0.254: IC15.11 122.31,25.75 123.85,24.21 123.85,21.81 127.45,18.21 141.8,18.21 145.35,21.76 145.35,25.61 145.95,26.21 149.4,26.21 149.39,26.21 J6.7
1_RXD
  Bottom 0.254: J6.2 146.84,24.82 146.85,24.06 148.95,21.96 150.55,21.96 151.4,22.81 151.4,32.76 149.55,34.61 144.15,34.61 143.1,33.51 127.7,33.51 127.1,32.91 127.1,31.66 125.09,29.65 IC15.5
1_TXD
  Bottom 0.254: IC15.9 123.16,27.05 126.95,23.31 141.75,23.31 146.05,27.61 147,27.61 146.98,27.59 J6.3
2_CTS
  Bottom 0.203: IC16.7 98.92,7.84 100.45,6.31 130.95,6.31 131,6.36
  Bottom 0.254: 131,6.36 131.2,6.56 134.45,6.56 135.2,7.31 135.2,8.41 135.9,9.11 140.2,9.11 141.55,7.76 J7.8
2_DCD  (via drill 0.3 pad 0.81)
  Top 0.203: v98.4,10.16 98.8,10.16 100,8.96 101.25,8.96 101.85,8.36 101.85,7.36 102.45,6.76 129.85,6.76 129.95,6.81
  Top 0.254: 129.95,6.81 132.9,9.81 139.05,9.81 140.3,8.56 140.3,7.01 139.8,6.51 135.15,6.51 133.9,5.26 J7.1
  Bottom 0.254: v98.4,10.16 98.2,10.01 98.03,9.79 IC16.4
2_DSR  (via drill 0.3 pad 0.81)
  Top 0.203: v99.1,8.61 99.1,7.66 100.45,6.31 130.5,6.31 130.55,6.36
  Top 0.254: 130.55,6.36 133.3,9.11 137.65,9.11 139,7.76 J7.6
  Bottom 0.254: IC16.6 98.83,8.49 v99.1,8.61
2_DTR
  Bottom 0.203: IC16.10 97.17,5.82 97.3,5.83
  Bottom 0.254: 97.3,5.83 97.7,5.83 98.97,5.03 99.95,4.01 134.55,4.01 135.2,4.66 135.2,6.01 136.45,7.26 136.45,7.81 J7.4
2_RI  (via drill 0.3 pad 0.81)
  Top 0.254: v98.55,7.01 98.25,6.71 98.25,4.96 99.8,3.41 142.3,3.41 144.1,5.21 144.09,5.22 J7.9
  Bottom 0.254: v98.55,7.01 98.35,7.16 98.31,7.19 IC16.8
2_RTS
  Bottom 0.254: IC16.11 97.31,5.19 97.67,5.18 98.53,4.66 99.65,3.41 139.7,3.41 J7.7
2_RXD
  Bottom 0.203: 130.35,6.81 130.3,6.76 102.45,6.76 101.85,7.36 101.85,8.36 100.61,9.59 99.08,9.59 98.35,9.16
  Bottom 0.254: IC16.5 96.44,9.14 96.45,9.16 98.35,9.16 | J7.2 134,7.81 | J7.2 | 130.35,6.81 131.35,7.81 J7.2
2_TXD  (via drill 0.3 pad 0.76)
  Top 0.254: v99.3,6.06 99.2,5.96 99.2,4.91 100.1,4.01 135.25,4.01 136.5,5.26 J7.3
  Bottom 0.203: IC16.9 97.69,6.54 98.35,6.16 99.2,6.16
  Bottom 0.254: 99.2,6.16 v99.3,6.06
2V9
  Bottom 0.203: 20.75,62.16 21.25,61.66 23.4,61.66 27.5,57.56 | 38.05,59.06 37.89,59.17 D5.3
  Bottom 0.254: 15.85,77.72 D4.3 | 15.85,68.9 15.85,73.31 | 15.85,73.31 15.85,77.72 | 15.85,68.9 D2.3 | 15.85,68.9 15.85,63.81 16.1,63.56 16.95,63.56 16.95,63.54 D1.3 20.27,63.54 20.75,63.06 20.75,62.16 | 15.85,73.31 D3.3 | 15.85,77.72 15.85,80.56 | 15.85,80.56 15.55,80.56 15.2,80.91 15.19,81.76 15.27,81.78 15.15,81.76 C52.1 14.88,81.78 R19.1 | D6.3 18.79,80.56 15.85,80.56 | 27.5,57.56 38.05,57.56 | 38.05,57.56 38.05,59.06 | R114.1 38.57,57.04 38.05,57.56
3V3OUT
  Top 0.254: 77,75.96 77.03,75.99 C13.+ | R112.2 75.59,69.02 74.3,70.31 71.47,70.31 71.45,70.31
  Top 0.813: 80.4,83.51 80.41,83.45 | 79.73,85.83 79.7,85.86 | 79.73,85.83 C15.+ | 79.9,85.66 79.73,85.83 | C13.+ 77.05,76.01 77.03,75.98
  Top 1.016: 79.9,85.66 80.4,85.16 80.4,83.51 80.4,77.26 79.14,75.99 C13.+ | 77.03,75.98 C14.+ 72.42,75.88 72.4,75.86 72.4,72.91 72.4,72.71 72,72.31 | 72,72.31 C16.+ | R14.1 71.47,70.31 71.47,71.78 72,72.31 | L1.2 84.26,84.15 84.25,84.16 83.59,83.5 80.41,83.45
  pour Top (isolate 0.254, no thermals): 80.5,87.06 82.15,87.06 83.4,85.81 83.4,82.46 82.05,81.11 82.05,77.31 79.65,74.91 75.1,74.91 73.05,72.86 71.3,72.86 71.3,77.06 78.6,77.06 79.8,78.26 79.8,86.41
4.000MHZ  (via drill 0.3 pad 0.81)
  Route2 0.254: J1.C28 10.07,79.22 7.05,76.23 7.05,42.28 8.25,41.08 v8.25,41.06
  Bottom 0.254: R51.2 12.58,39.28 12,39.86 9.45,39.86 v8.25,41.06
5V_CPLD  (via drill 0.3 pad 0.81)
  Top 0.254: v112.5,47.46 112.53,47.43 | v106.5,47.31 106.5,47.41 106.53,47.38 | 106.35,57.26 v106.35,57.11 | v112.5,59.91 112.55,59.96 112.53,59.98 | 107.53,60.88 IC23.98
  Top 0.305: IC23.57 119.42,50.66 118.78,50.01 v118.8,49.96 118.78,49.96 118.78,48.36 119.47,47.66 IC23.51 | 112.53,47.43 IC23.38 | IC23.26 106.53,47.38 | IC23.5 105.95,57.66 106.35,57.26 | 112.53,59.98 IC23.88 | 107.53,60.88 107.53,60.76 108.28,60.01 v108.9,60.01
  Bottom 0.406: v108.9,60.01 109.1,60.01 109.85,59.26 109.85,58.36 109.87,58.34 C95.2 | v112.5,59.91 112.5,58.63 C96.2 | C97.2 117.1,50.96 117.4,50.66 118.45,50.66 118.8,50.31 v118.8,49.96 118.8,48.61 118.86,48.53 C101.2 | C98.2 113.03,47.99 v112.5,47.46 | C99.2 107.03,47.29 v106.5,47.31 | v106.5,47.31 v106.5,47.3 106.5,47.29 106.5,47.28 v106.5,47.31 | C100.2 107.81,56.27 107.65,56.43 106.65,56.43 106.35,56.73 v106.35,57.11
  Bottom 0.813: v106.5,47.31 107.2,47.31 108.58,48.68 110.45,48.68 111.67,47.46 v112.5,47.46 112.46,47.42 R158.1
  pour Bottom (isolate 0.254): 105.45,59.78 105.45,44.96 105.88,44.53 117.65,44.53 120.38,47.26 120.38,56.83 116.35,60.86 106.53,60.86
5V_SREG  (via drill 0.3 pad 0.81)
  Top 0.254: IC5.7 84.55,62.61 84.56,62.6 84.56,61.82 84.55,61.76 C12.1 | IC5.1 80.23,62.33 79.68,62.88 C11.1
  Top 0.305: IC5.1 80.65,59.78 80.8,59.63 81.1,59.63 | 83.9,59.63 81.1,59.63 | 83.9,59.63 84.55,59.63 84.55,61.76 IC5.7 | 83.9,59.63 IC5.6 | 81.1,59.63 81.1,61.26 81.3,61.46 IC5.2
  Top 0.406: C10.+ 87.61,53.95 84.55,57.01 84.55,59.63 | v90.8,52.01 v90.8,52.86 v90.8,53.71 90.8,54.61 90.3,54.31
  Top 0.813: 88.3,68.98 89.78,68.98 90.3,68.46 90.3,54.31 91.45,55.46 91.45,68.91 90.25,70.11 88.1,70.11 88.08,70.09 C9.+
  Top 1.016: 88.3,68.98 88.3,68.86 88.1,69.01 88.1,69.58 C9.+ | 90.3,54.31 89.8,53.81 88.25,53.81 88.19,53.75 C10.+
  Route15 0.61: v90.8,52.86 v90.8,52.01
  Route15 1.016: v74.75,65.31 v75.67,65.31 v76.58,65.31 76.83,65.31 80.6,61.53 80.6,59.86 81.3,59.16 85.3,59.16 v90.8,53.71 v90.8,52.86
  Bottom 0.406: 74.63,65.33 v74.75,65.31 | 70.11,67.8 70.1,67.81 | 70.11,67.8 L6.1 | 70.13,67.78 70.11,67.8 | 70.65,69.91 C62.1
  Bottom 0.61: L2.1 70.13,65.78 70.15,65.66
  Bottom 0.813: L2.1 70.13,67.78 | L6.1 70.11,68.52 70.65,69.06 70.65,69.91
  Bottom 1.016: v74.75,65.31 v75.67,65.31 v76.58,65.31 | 74.3,65.66 74.63,65.33
  Bottom 1.27: 70.15,65.66 74.3,65.66
  pour Top (isolate 0.305, no thermals): 80.55,62.46 86.3,62.46 86.3,57.01 91.75,57.01 91.75,51.51 88.2,51.51 82.35,57.31 80,57.31 79,58.36 79,60.96 77.2,62.76 77.2,63.01 80,63.01
5VKBD
  Bottom 0.254: 151.2,77.76 J8.4 | 146.38,81.01 146.4,81.01 146.37,80.98
  Bottom 0.406: L3.1 138.6,96.81 138.77,96.78 | 138.8,96.76 138.78,96.78 L3.1 | 138.77,96.78 138.75,96.76 | L3.1 138.77,96.78
  Bottom 0.61: J8.4 | 146.38,81.01 147.95,81.01 151.2,77.76 | 146.38,81.01 146.38,85.46 138.8,93.01 J9.1 138.8,96.76 | C87.1 144.69,97.82 144.1,98.41 139.1,98.41 138.6,97.91 138.6,96.81 | R69.2 144.07,80.43 144.65,81.01 146.38,81.01 | 146.37,80.98 R68.2
+1V2  (via drill 0.3 pad 0.81)
  Top 0.254: IC21.P49 67.25,33.26 v68,34.01 | IC21.P61 73.25,33.01 v72.3,34.01 | IC21.P133 66.75,52.71 v67.45,52.01 | IC21.P121 72.75,52.56 v72.2,52.01
  Top 0.61: 50.68,74.73 v50.7,74.56 v51.8,74.56
  Top 0.813: 50.68,74.73 R16.2
  Route15 0.61: 72.2,50.81 v72.2,52.01
  Route15 0.813: 70.8,49.46 70.85,49.46 72.2,50.81 | 67.45,49.46 v67.45,52.01
  Route15 1.016: 70.8,49.46 67.45,49.46 56.8,49.46 v53.45,52.81 v53.45,53.71
  Bottom 0.406: 67.72,50.54 67.7,50.56 | C46.1 67.72,50.54 | 67.72,50.54 67.75,50.51 | C41.1 69.45,50.51 C41.1 | C45.1 71.22,50.49 | 69.7,35.56 C43.1 | 71.43,35.53 71.45,35.51 | 71.43,35.53 C39.1 | C39.1 71.43,35.53 | C44.1 73.11,35.55 | v72.3,34.01 72.3,34.06
  Bottom 0.61: C46.1 67.75,51.71 v67.45,52.01 | 67.75,50.51 69.45,50.51 | C41.1 C45.1 | 71.22,50.49 C40.1 | v72.2,52.01 72.55,51.66 72.55,50.51 | v68,34.01 C42.1 69.7,35.56 | C43.1 C39.1 | C39.1 73.11,35.55 | 72.3,34.06 72.65,34.41 72.65,35.51 | C50.1 v70.95,40.66
  Bottom 0.813: v50.7,74.56 v51.8,74.56 51.8,74.51 53.45,72.86 v53.45,53.71 v53.45,52.81
  pour Top (isolate 0.254): 66.75,53.01 66.75,52.16 67.25,51.66 67.25,33.06 73.2,33.06 73.2,33.46 72.85,33.81 72.85,50.06 72.75,50.16 72.75,53.01
+2V5  (via drill 0.3 pad 0.81)
  Top 0.254: IC21.P48 66.75,33.61 v66.35,34.01 | IC21.P62 73.75,33.81 v73.85,34.01 | IC21.P134 66.25,52.26 v66,52.01 | v73.85,52.01 73.85,51.96 73.25,52.56 IC21.P120
  Top 0.813: R15.2 62.32,75.34 62.35,75.31 62.4,75.36 v63.7,75.36 v64.65,75.36
  Route15 0.254: v62.85,64.91 62.9,64.91
  Route15 0.406: 71.55,53.06 71.25,52.76 71.25,51.71 70.85,51.31 | v63.3,25.56 67.35,25.56 67.35,25.51
  Route15 0.61: v73.85,52.01 72.8,53.06 71.55,53.06 | 70.85,51.31 69.45,51.31 68.95,51.81 68.95,52.51 68.35,53.11 66,53.11
  Route15 0.813: v66,52.01 66,53.11 | v66.35,34.01 66.35,33.31 67.3,32.36 69.3,32.36 | 69.3,32.36 73.1,32.36 73.85,33.11 v73.85,34.01 | v67.35,25.01 67.35,25.51 69.3,27.46 69.3,32.36
  Route15 1.016: 66,53.11 63.8,55.31 v63.8,64.91 v62.85,64.91
  Bottom 0.254: R4.1 61.59,25.35 61.9,25.66 63.2,25.66 v63.3,25.56 | v67.35,25.01 65.95,25.01
  Bottom 0.406: C38.1 65.54,49.45 66,49.91 66,50.36 66.1,50.46 66.1,51.86 66,51.96 v66,52.01 | C37.1 65.54,47.52 | C36.1 75.08,49.38 74.85,49.61 74.85,50.46 74.55,50.76 74.55,51.31 v73.85,52.01 | C35.1 75.12,47.59 75.08,47.63 | C34.1 66.04,36.57 66.05,36.56 | C34.1 | C34.1 66.35,36.26 v66.35,34.01 | 75.35,36.56 C32.1 75.63,36.58 75.7,36.56 75.7,34.71 75,34.01 v73.85,34.01 | 67.6,43.61 67.63,43.64 | 65.95,25.01 R6.1
  Bottom 0.61: 65.54,47.52 C38.1 | 75.08,49.38 75.08,47.63 | 66.04,36.57 C33.1 | 75.35,36.56 C31.1 | 67.63,43.64 C3.1
  Bottom 0.813: v66,43.61 67.6,43.61 v74,43.61 | v66,42.41 v74,42.41
  Bottom 1.016: v64.65,75.36 v63.7,75.36 63.7,64.91 | 63.7,64.91 v62.85,64.91 | v63.8,64.91 63.7,64.91
  pour Top (isolate 0.254): 66.2,52.96 66.2,51.81 66.7,51.31 66.7,33.01 65.25,33.01 65.25,52.96
  pour Top (isolate 0.254): 73.75,33.06 73.75,33.71 73.4,34.06 73.4,50.36 73.3,50.46 73.3,52.96 74.7,52.96 74.7,52.06 74.75,51.96 74.75,33.06
+3V3  (via drill 0.3 pad 0.76, 0.3 pad 0.81)
  Top 0.254: 21.2,27.11 21.17,27.03 IC6.24 21.23,27.03 21.25,27.01 | 20.98,37.99 IC9.24 | 20.98,37.99 21.2,38.06 | 21.29,49 IC7.24 21.26,49 21.3,48.96 | 20.98,37.99 21.27,37.99 21.3,37.96 | 21.3,37.41 21.28,37.34 IC9.23 | 21.3,48.46 21.26,48.35 IC7.23 | IC8.24 22.16,60.02 v22.5,59.66 22.19,59.37 IC8.23 | v64.25,34.01 IC21.P43 | v69.75,33.61 IC21.P54 | IC21.P66 75.75,33.51 v76.3,34.06 | v60.6,35.21 60.65,35.21 60.61,35.25 IC21.P34 | v60.6,42.76 61.55,43.51 60.64,42.75 IC21.P19 | IC21.P75 79.44,35.25 v79.4,35.21 | IC21.P91 79.44,43.25 v79.4,43.21 | 79.36,50.75 v79.4,50.71 | IC21.P106 79.36,50.75 | 79.36,50.75 79.35,50.76 | v75.75,52.41 IC21.P115 | v70.25,52.41 IC21.P126 | v64.25,52.01 IC21.P138 | IC21.P3 v60.59,50.75 v60.6,50.76 | D10.2 107.01,28.27 106.3,27.56 v106.25,27.56 | IC14.23 88.17,41.14 88.35,40.96 88.35,40.49 88.2,40.46 | IC6.23 21.22,26.38 21.25,26.41 | R154.2 94.81,49.7 v95.55,48.96
  Top 0.3: 23.1,59.66 23.2,59.61 23.4,59.66
  Top 0.406: L4.2 70.65,17.56 70.7,17.61 v72.5,17.61 | v50.2,10.26 50.2,10.31 50.23,10.34 L5.2 | v19.2,26.96 19.5,27.26 21.2,27.26 | C54.1 21.15,28.86 21.2,28.81 21.2,27.26 | 21.2,27.26 21.2,27.11 | v19.5,38.31 19.75,38.56 21.2,38.56 | C60.1 20.99,39.87 21.2,39.81 21.2,38.56 | 21.2,38.06 21.2,38.56 | 21.35,50.91 C56.1 | 21.29,49 21.25,49.16 | 21.25,50.81 21.35,50.91 | 21.3,37.41 21.3,37.96 | 21.3,48.96 21.3,48.46 | v88.83,37.46 88.9,37.43 88.98,37.43 C72.1 88.98,39.88 88.37,40.49 88.35,40.49 IC14.24 | 21.25,27.01 21.25,26.41 | IC11.9 30.86,94.02 v30.88,94.01 | IC11.27 29.59,87.75 v29.75,87.91 | IC10.9 30.81,80.57 30.8,80.26 30.8,78.76 v30.6,78.61 | 29.77,72.96 v29.75,72.83 29.59,72.67 IC10.27 | 25.53,59.68 | 25.53,59.68 C63.1 | 25.53,59.68 25.55,59.66 | 21.35,50.91 21.35,51.31 | 21,29.06 22.6,29.06 v22.65,29.21 | 21.2,27.26 22.65,27.26 | 25.15,27.26 25.8,26.61 | v19.55,49.36 19.8,49.11 21.3,49.11
  Top 0.6: C63.1 25.65,59.81
  Top 0.61: 21.25,49.16 21.25,50.81 | 21.35,51.31 22.15,51.31 22.55,51.71 v22.75,51.71 v22.75,52.66 | v29.75,87.91 29.75,91.81 30.85,92.91 30.85,94.01 | v25.8,26.66 25.75,26.66 | 25.15,27.26 25.23,27.26 | v30.3,49.51 30.25,49.46 27.3,52.41 v27.25,52.41 | v26.55,51.76 26.6,51.76 29.6,48.76 | v29.6,77.21 29.75,77.06 v29.75,73.86 29.75,72.86
  Top 0.8: 25.65,59.81 v27.3,59.81 | C64.1 25.53,59.68 | v22.5,59.66 23.1,59.66
  Top 0.813: v73.55,67.31 v74.55,67.31 v73.55,67.31 | v72.5,67.31 73.4,67.31 | 73.4,67.31 v73.55,67.31 | 73.4,67.31 73.4,68.96 | v26.85,26.66 v25.8,26.66 25.23,27.26 | v22.65,29.21 22.65,27.26 25.15,27.26
  Top 1.016: 73.4,68.96 R14.2
  Route2 0.61: v29.75,72.83 29.75,72.81
  Route2 0.813: 50.25,91.31 50.25,91.56 | 50.25,91.56 v49.75,91.56 | 50.25,91.56 v50.25,92.61 | 50.25,91.56 50.7,91.56 | v28.15,88.26 28.5,87.91 v29.75,87.91
  Route2 1: v29.75,87.91 29.75,84.46 30.5,83.71 30.5,78.11 29.75,77.41 v29.75,73.86 v29.75,72.83
  Route2 1.27: J4.56 J4.55 48.6,81.76 49.45,82.61 49.45,90.51 50.25,91.31
  Route15 0.254: v95.55,48.96 93.4,51.11 90.03,51.11 88.83,52.31 86.45,52.31 86.1,52.66 86.1,54.71 85.45,55.36 83.35,55.36 79.4,51.41 v79.4,50.71
  Route15 0.813: v125.35,89.91 125.4,89.96 | v106.25,27.56 103.12,30.71 96.42,30.71 95.3,29.58 89.53,29.58 85.6,33.53 85.6,36.86 86.2,37.46 v88.83,37.46 | v73.55,67.31 v74.55,67.31 v72.5,67.31 72.5,63.31 75.75,60.06 v75.75,52.41
  Route15 1.016: 133.45,89.96 v133.45,70.56 | 131.4,89.96 133.45,89.96 | 131.4,89.96 v131.4,93.31 | 133.45,89.96 v136.65,89.96 | 125.4,89.96 131.4,89.96 | v125.35,89.91 114.8,89.91 113.6,88.71 83,88.71 v82.45,89.16 v81.45,89.16
  Bottom 0.203: v30.6,78.61 30.65,78.61
  Bottom 0.254: D13.2 | D13.2 66.45,8.76 | 86.85,87.06 86.86,87.07 R75.2 | R76.2 89.52,87.09 89.54,87.07 89.55,87.06 | 92.24,87.02 92.25,87.01 | 92.24,87.02 R77.2 | 92.17,87.09 92.24,87.02 | 94.8,87.06 R78.2 | 97.46,87.05 97.5,87.01 | 97.46,87.05 R79.2 | 97.43,87.08 97.46,87.05 | R80.2 99.99,87.05 | R81.2 102.63,87.04 102.65,87.06 102.64,87.07 | IC1.19 58.74,15 58.75,15.01 | 58.09,15.01 58.75,15.01 | 58.75,15.01 59.25,15.01 59.39,14.87 IC1.18 | C49.1 56,19.01 | 54.95,22.61 v54.9,22.66 | C47.1 56,17.06 56.03,17.03 | R5.2 68.39,19.1 v68.75,19.46 | v136.65,89.96 R72.2 | v125.35,89.91 125.3,89.91 125.33,89.94 R73.2 | R7.2 130.15,96.51 130.2,96.46 130.85,96.46 131.4,95.91 v131.4,93.31 | R93.2 | 41.92,59.81 41.92,58.99 v42,58.91 | R74.2 81.41,89.2 v81.45,89.16 | v27.3,59.81 27.35,59.81 | 30.88,63.34 IC12.37 | 41.92,59.81 R20.1 | D5.2 D5.1 | D5.1 40.09,60.1 40.1,60.11 | 41.92,59.81 41.85,59.81 41.88,59.83 D5.1 | R155.2 63.15,8.31 65,10.16 v65,10.18 65.58,10.18 66.2,9.56 D13.2 | R115.2 38.68,95.08 38.3,95.46 32.3,95.46 30.85,94.01 v30.88,94.01
  Bottom 0.406: C58.1 19.57,58.33 19.75,58.36 21.2,58.36 v22.5,59.66 | v133.45,70.56 133.4,70.56 133.41,70.47 R82.2 | R93.2 86.85,87.06 | R75.2 89.54,87.07 | R76.2 92.17,87.09 | R77.2 94.8,87.06 | R78.2 97.43,87.08 | R79.2 99.99,87.05 | R80.2 102.64,87.07 | 64.85,52.91 64.9,52.96 70.25,52.96 75.35,52.96 | 69.75,33.06 75.45,33.06 | 75.45,33.06 75.5,33.06 | 76.3,33.86 v76.3,34.06 | C20.1 69.67,53.89 69.7,53.86 | C19.1 64.84,54.22 64.9,54.16 | v79.4,50.71 79.27,50.84 | C26.1 62.25,42.76 | 77.75,43.21 C29.1 | 79.38,35.19 v79.4,35.21 | 75.45,33.06 75.53,32.98 | 68.84,33.05 68.85,33.06 64.25,33.06 | C24.1 64.21,31.67 64.25,31.71 | v60.6,35.21 60.6,35.16 60.48,35.28 | C49.1 55.94,17.02 55.95,17.01 | 55.95,17.01 C47.1 56,17.01 | 55.95,17.01 55.92,16.98 C48.1 55.92,15.04 55.95,15.01 58.09,15.01 IC1.20 | 56,19.01 56,21.56 54.95,22.61 | 81.45,87.06 R93.2 | v30.88,94.01 31.1,94.01 31.55,93.56 C66.1 | v29.75,87.91 29.68,87.91 29.25,88.33 C65.1 | 30.65,78.61 30.75,78.61 31.27,78.09 31.27,77.14 31.6,76.91 C68.1
  Bottom 0.61: v64.25,52.01 64.25,52.31 64.85,52.91 | v75.75,52.41 75.75,52.56 75.35,52.96 C21.1 | v70.25,52.41 70.25,52.96 69.7,52.96 69.7,53.86 | v64.25,34.01 64.25,33.06 64.25,31.71 | 68.85,33.06 69.75,33.06 v69.75,33.61 | 75.5,33.06 76.3,33.86 | 64.9,52.96 64.9,54.16 | C27.1 60.97,51.13 v60.6,50.76 | 79.27,50.84 C28.1 | 77.75,43.21 v79.4,43.21 | C30.1 79.38,35.19 | 75.53,32.98 C22.1 | 68.84,33.05 C23.1 | C25.1 60.48,35.28 | v60.6,42.76 C26.1 | 27.35,59.81 30.88,63.34 | v29.75,72.83 v29.75,73.86 29.75,75.41 | 29.75,75.41 29.75,77.76 v30.6,78.61 | C67.1 27.95,75.41 29.75,75.41
  Bottom 0.813: v81.45,89.16 v82.45,89.16 | v74.55,67.31 v73.55,67.31 v72.5,67.31 | v69.55,89.76 v70.55,89.76 | v69.55,89.76 v68.55,89.76 | v69.55,89.76 69.55,87.71 71.2,86.06 81.45,86.06
  Bottom 1.016: v73.55,67.31 73.55,67.71
  Bottom 1.27: v81.45,89.16 81.45,87.06 81.45,86.06 81.45,80.26 73.55,72.36 73.55,67.71
  other vias: 50.75,91.56 29.6,48.81
  pour Top: 64.65,52.91 64.65,33.11 60.1,33.11 60.1,52.91
  pour Top: 75.3,52.91 79.9,52.91 79.9,33.06 75.3,33.06
  pour Route15 (isolate 0.254): 18.7,95.26 62.1,95.26 66.85,90.51 86.65,90.51 86.65,85.86 64.4,85.86 61.85,88.41 45.15,88.41 45.15,76.26 86.6,76.26 86.72,33.53 73.6,20.51 73.6,9.71 48.95,9.71 48.95,16.66 41.05,16.66 41.05,15.51 16.25,15.51 16.25,30.56 20.5,34.76 20.5,38.16 19.2,38.16 18.7,38.66
  pour Bottom: 65.45,82.56 65.45,89.41 66.85,90.81 81.75,90.81 82.85,89.71 82.85,72.56 75.95,65.66 71.1,65.66 71.1,67.81 72.95,67.81 72.95,73.46 71.75,74.66 71.75,80.56 69.75,82.56
+5V  (via drill 0.3 pad 0.3, 0.3 pad 0.81)
  Top 0.254: IC18.9 105.47,19.08 105.5,19.06 v105.5,17.26 | 96.6,19.11 IC18.16 | IC8.1 15.99,60.02 v16.4,60.01 | IC9.1 14.92,37.99 14.9,38.01 14.2,38.01 14.15,38.06 14.1,38.06 | v16.5,38.31 16.45,38.36 | v85.15,17.21 85.15,17.16 85.14,17.17 IC20.10 | IC19.10 v119.19,17.26 v119.2,17.26 | 111.55,18.56 111.55,19.11 | C91.1 109.51,18.47 109.6,18.56 | R125.2 150.48,44.79 153.6,47.91 v153.6,52.41 | v120.25,46.66 122.55,46.66 123.3,45.91 123.3,45.36 123.37,44.99 R140.2 123.37,44.98 123.4,45.01 123.39,45.02 R126.2 | v120.25,46.66 120.22,46.63 | v120.25,46.66 | R127.2 v136.14,32.25 v136.15,32.26 | R128.2 136.13,29.68 v136.15,29.66 | R129.2 v136.15,27.16 | R130.2 136.12,24.59 v136.15,24.56 | R131.2 136.19,22.02 v136.15,22.01 | R133.2 136.12,16.93 v136.15,16.96 | R122.2 135.39,65.2 137.2,67.01 141.25,67.01 v141.55,67.31 | R120.2 136.12,50.04 v136.15,50.01
  Top 0.305: J5.13 147.6,52.36 147.1,51.86 C73.1
  Top 0.406: 96.6,19.11 v96.6,17.36 96.63,17.74 C90.1 | J1.C8 13.73,28.42 | 13.73,28.42 13.75,28.42 13.85,28.41 | 13.73,28.42 13.85,28.41 | 13.85,28.41 13.85,28.66 14.05,28.86 C53.1 | IC6.1 14.03,27.03 13.85,27.21 13.85,28.41 | C59.1 14.99,38.8 15,38.56 | 15,38.56 14.25,38.56 14.1,38.41 14.1,38.06 | 16.45,38.36 16.25,38.56 15,38.56 | C55.1 14.1,50.91 13.9,50.71 | 13.9,50.71 13.9,49.01 15,49.01 IC7.1 | v12.8,49.01 12.8,49.61 13.9,50.71 | v76.2,20.11 76.25,20.16 | C92.1 75.74,19.65 v76.2,20.11 | v76.2,20.11 77.4,20.11 77.5,20.01 77.5,19.06 IC20.16 | C91.1 109.69,18.55 110.7,18.56 | v111.2,17.46 111.05,17.46 110.7,17.81 110.7,18.56 | 111.55,19.11 IC19.16 | C79.1 111.55,28.25 111.55,28.26 110.45,29.36 v110.45,29.56 | 110.7,18.56 109.6,18.56 | 110.7,18.56 111.55,18.56 | C84.1 87.76,8.46 v86.85,8.46
  Top 0.813: 23.38,13.58 v23.4,13.56 | v10.5,93.56 v10.5,94.51 | v10.5,94.51 v10.5,95.46 | v10.5,94.51 v10.5,94.52 | D20.K 96.1,28.56 96.46,27.67 | 98.24,27.67 98.25,28.41 v98.25,28.11 v98.25,27.11 v98.25,26.11 | v151.1,11.46 v153.85,11.46 | v151.1,36.71 v153.85,36.71 | v69.35,91.71 v68.55,91.71 v67.75,91.71 67.75,91.66 66.1,90.01 58.75,90.01 58.11,89.37 58.11,86.96
  Top 1.016: v23.4,12.56 v23.4,13.56 v23.4,14.56 | C17.+ 23.38,13.58 | v10.5,94.52 C18.+ | C5.1 58.1,87.16 58.1,86.96 58.11,86.96 58.11,85.05 58.85,84.31 IC3.3
  Top 1.27: 32.05,6.46 32.65,6.11 33.55,6.11 33.55,6.09 F1.1 33.2,6.01 33.75,6.56 v37.6,6.56 v38.6,6.56 | 96.46,27.67 98.24,27.67 | v38.6,6.56 38.12,5.88 39.48,5.88 39.48,4.86 D21.K | v38.6,6.56 v39.6,6.56
  Route2 0.61: v12.15,30.36 12.9,29.66
  Route2 0.813: v10.5,93.56 v10.5,94.51 | J4.58 44.05,84.31 | J4.58 | J4.57 | v16.5,38.31 14.55,36.36 14.55,31.31 12.9,29.66 11.65,28.41 10.45,28.41
  Route2 1.27: v10.5,94.51 v10.5,95.46 11.5,96.41 35.65,96.41 38.95,93.11 38.95,88.01 42.65,84.31 J4.58 J4.57
  Route15 0.254: 18.35,99.36 18.35,97.81 18.35,95.96
  Route15 0.813: v69.35,91.71 v68.55,91.71 v67.75,91.71
  Route15 1.422: 7.75,84.31 7.75,93.56 12,97.81 18.35,97.81 68.55,97.81 | 68.55,97.81 90.3,97.81 | J1.C30 10.4,84.3 10.4,84.31 7.75,84.31 | 68.55,97.81 v68.55,91.71 | J1.C8 10.4,28.41 10.38,28.42 J1.A8 5.32,28.42 5.3,28.41 1.95,28.41 | J1.C3 10.4,15.71 10.38,15.72 J1.A3 5.34,15.75 5.35,15.76 2.5,15.76 1.95,16.31 1.95,28.41 | 7.75,84.31 2.4,84.31 1.9,83.81 1.95,28.41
